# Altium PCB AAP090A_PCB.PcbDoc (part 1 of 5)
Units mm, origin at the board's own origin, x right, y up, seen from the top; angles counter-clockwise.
Board outline 160 x 130 mm, 4 copper layers (Top Layer, Signal Layer 1, Signal Layer 2, Bottom Layer), stack 1.567 mm thick; 507 components, 275 nets, 1462 pads, 1041 vias.
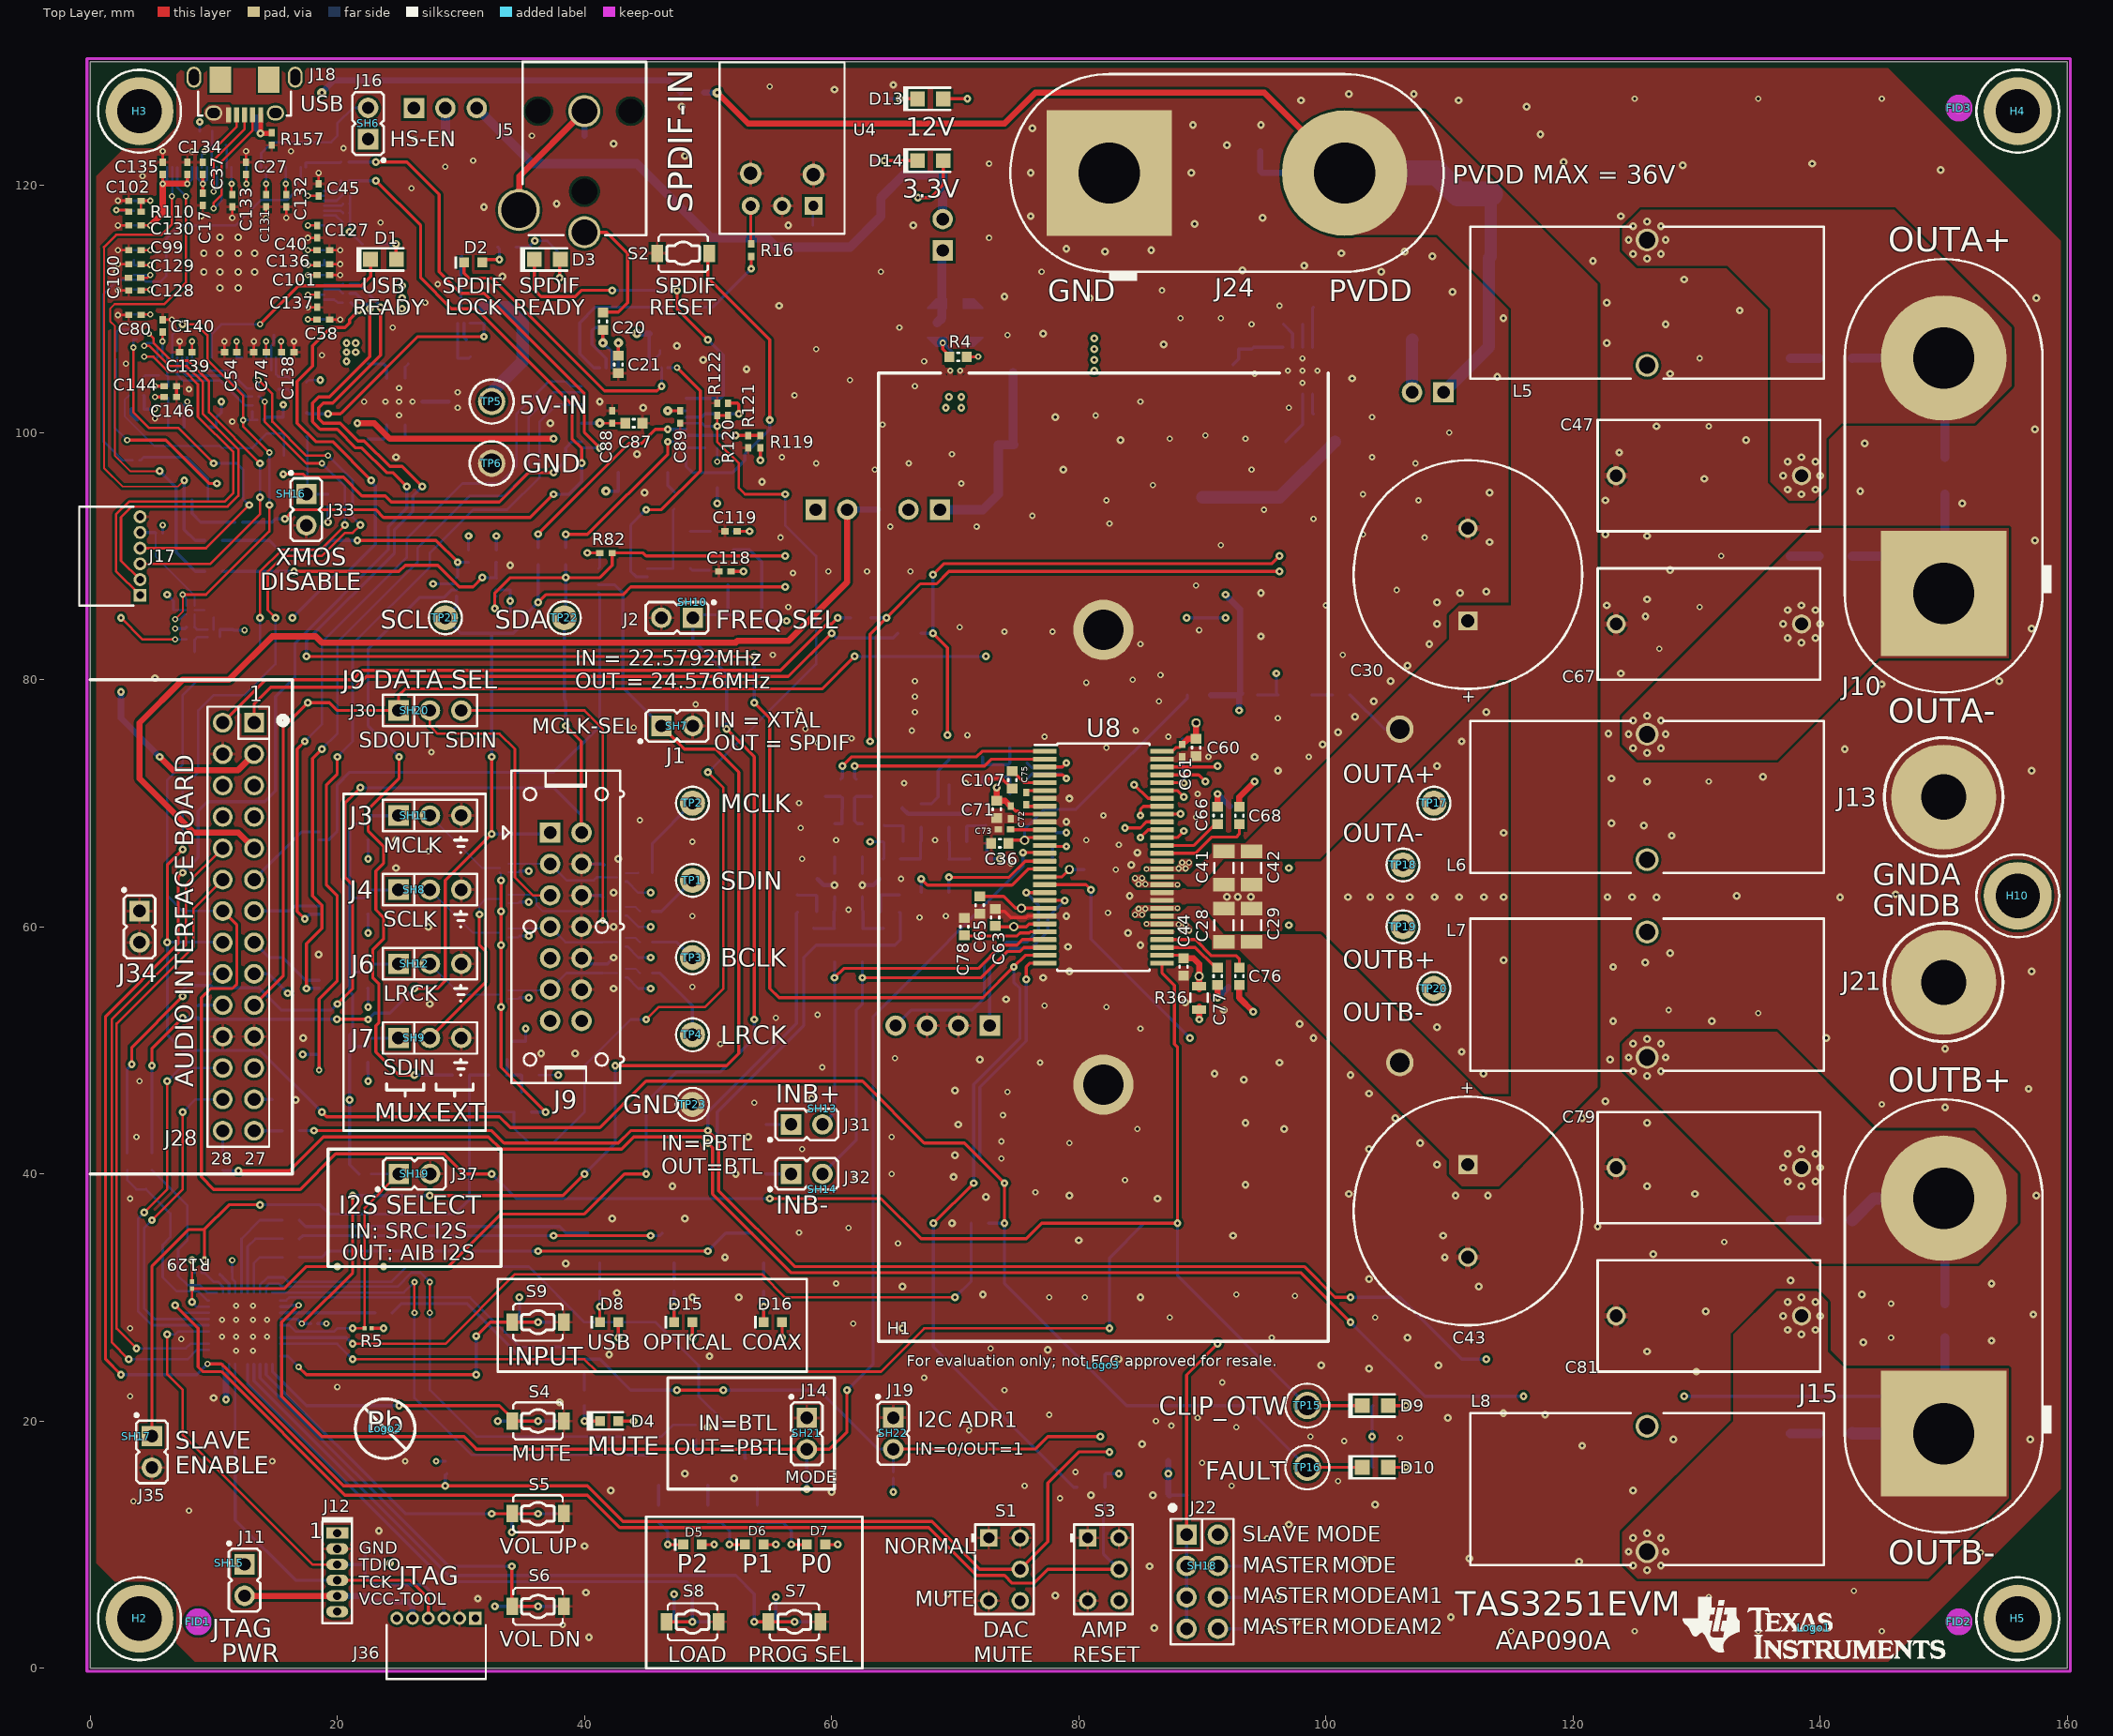
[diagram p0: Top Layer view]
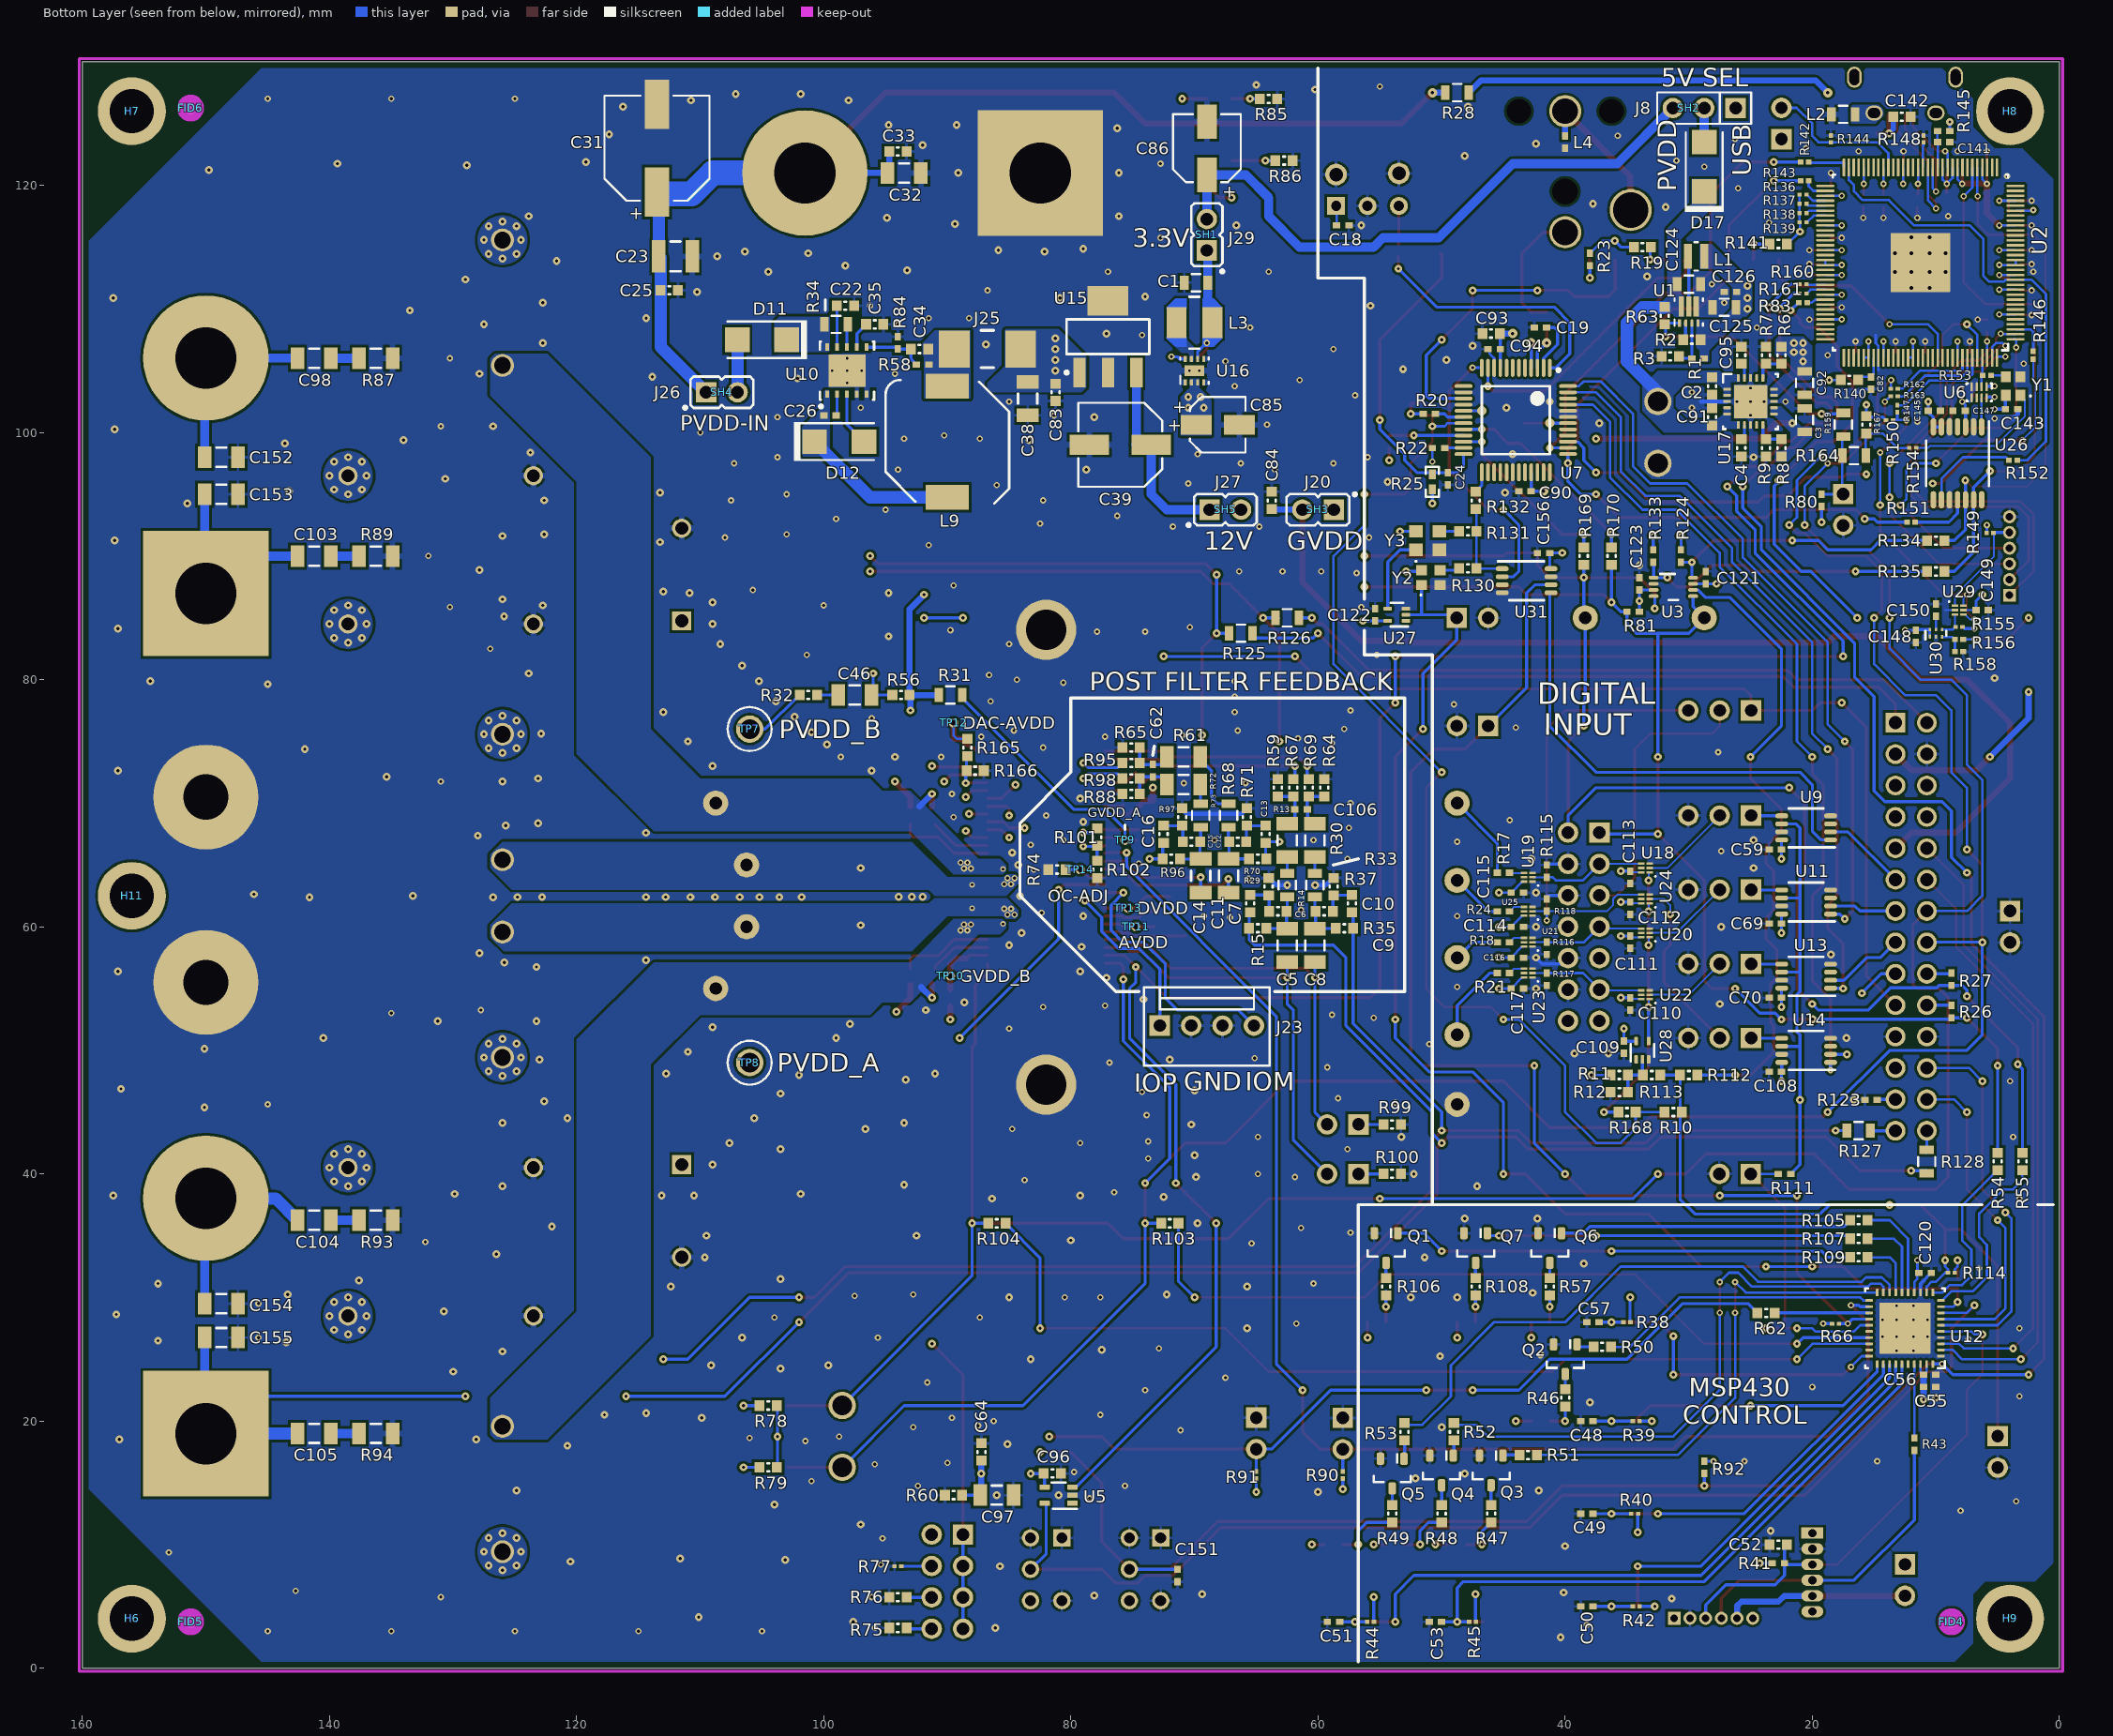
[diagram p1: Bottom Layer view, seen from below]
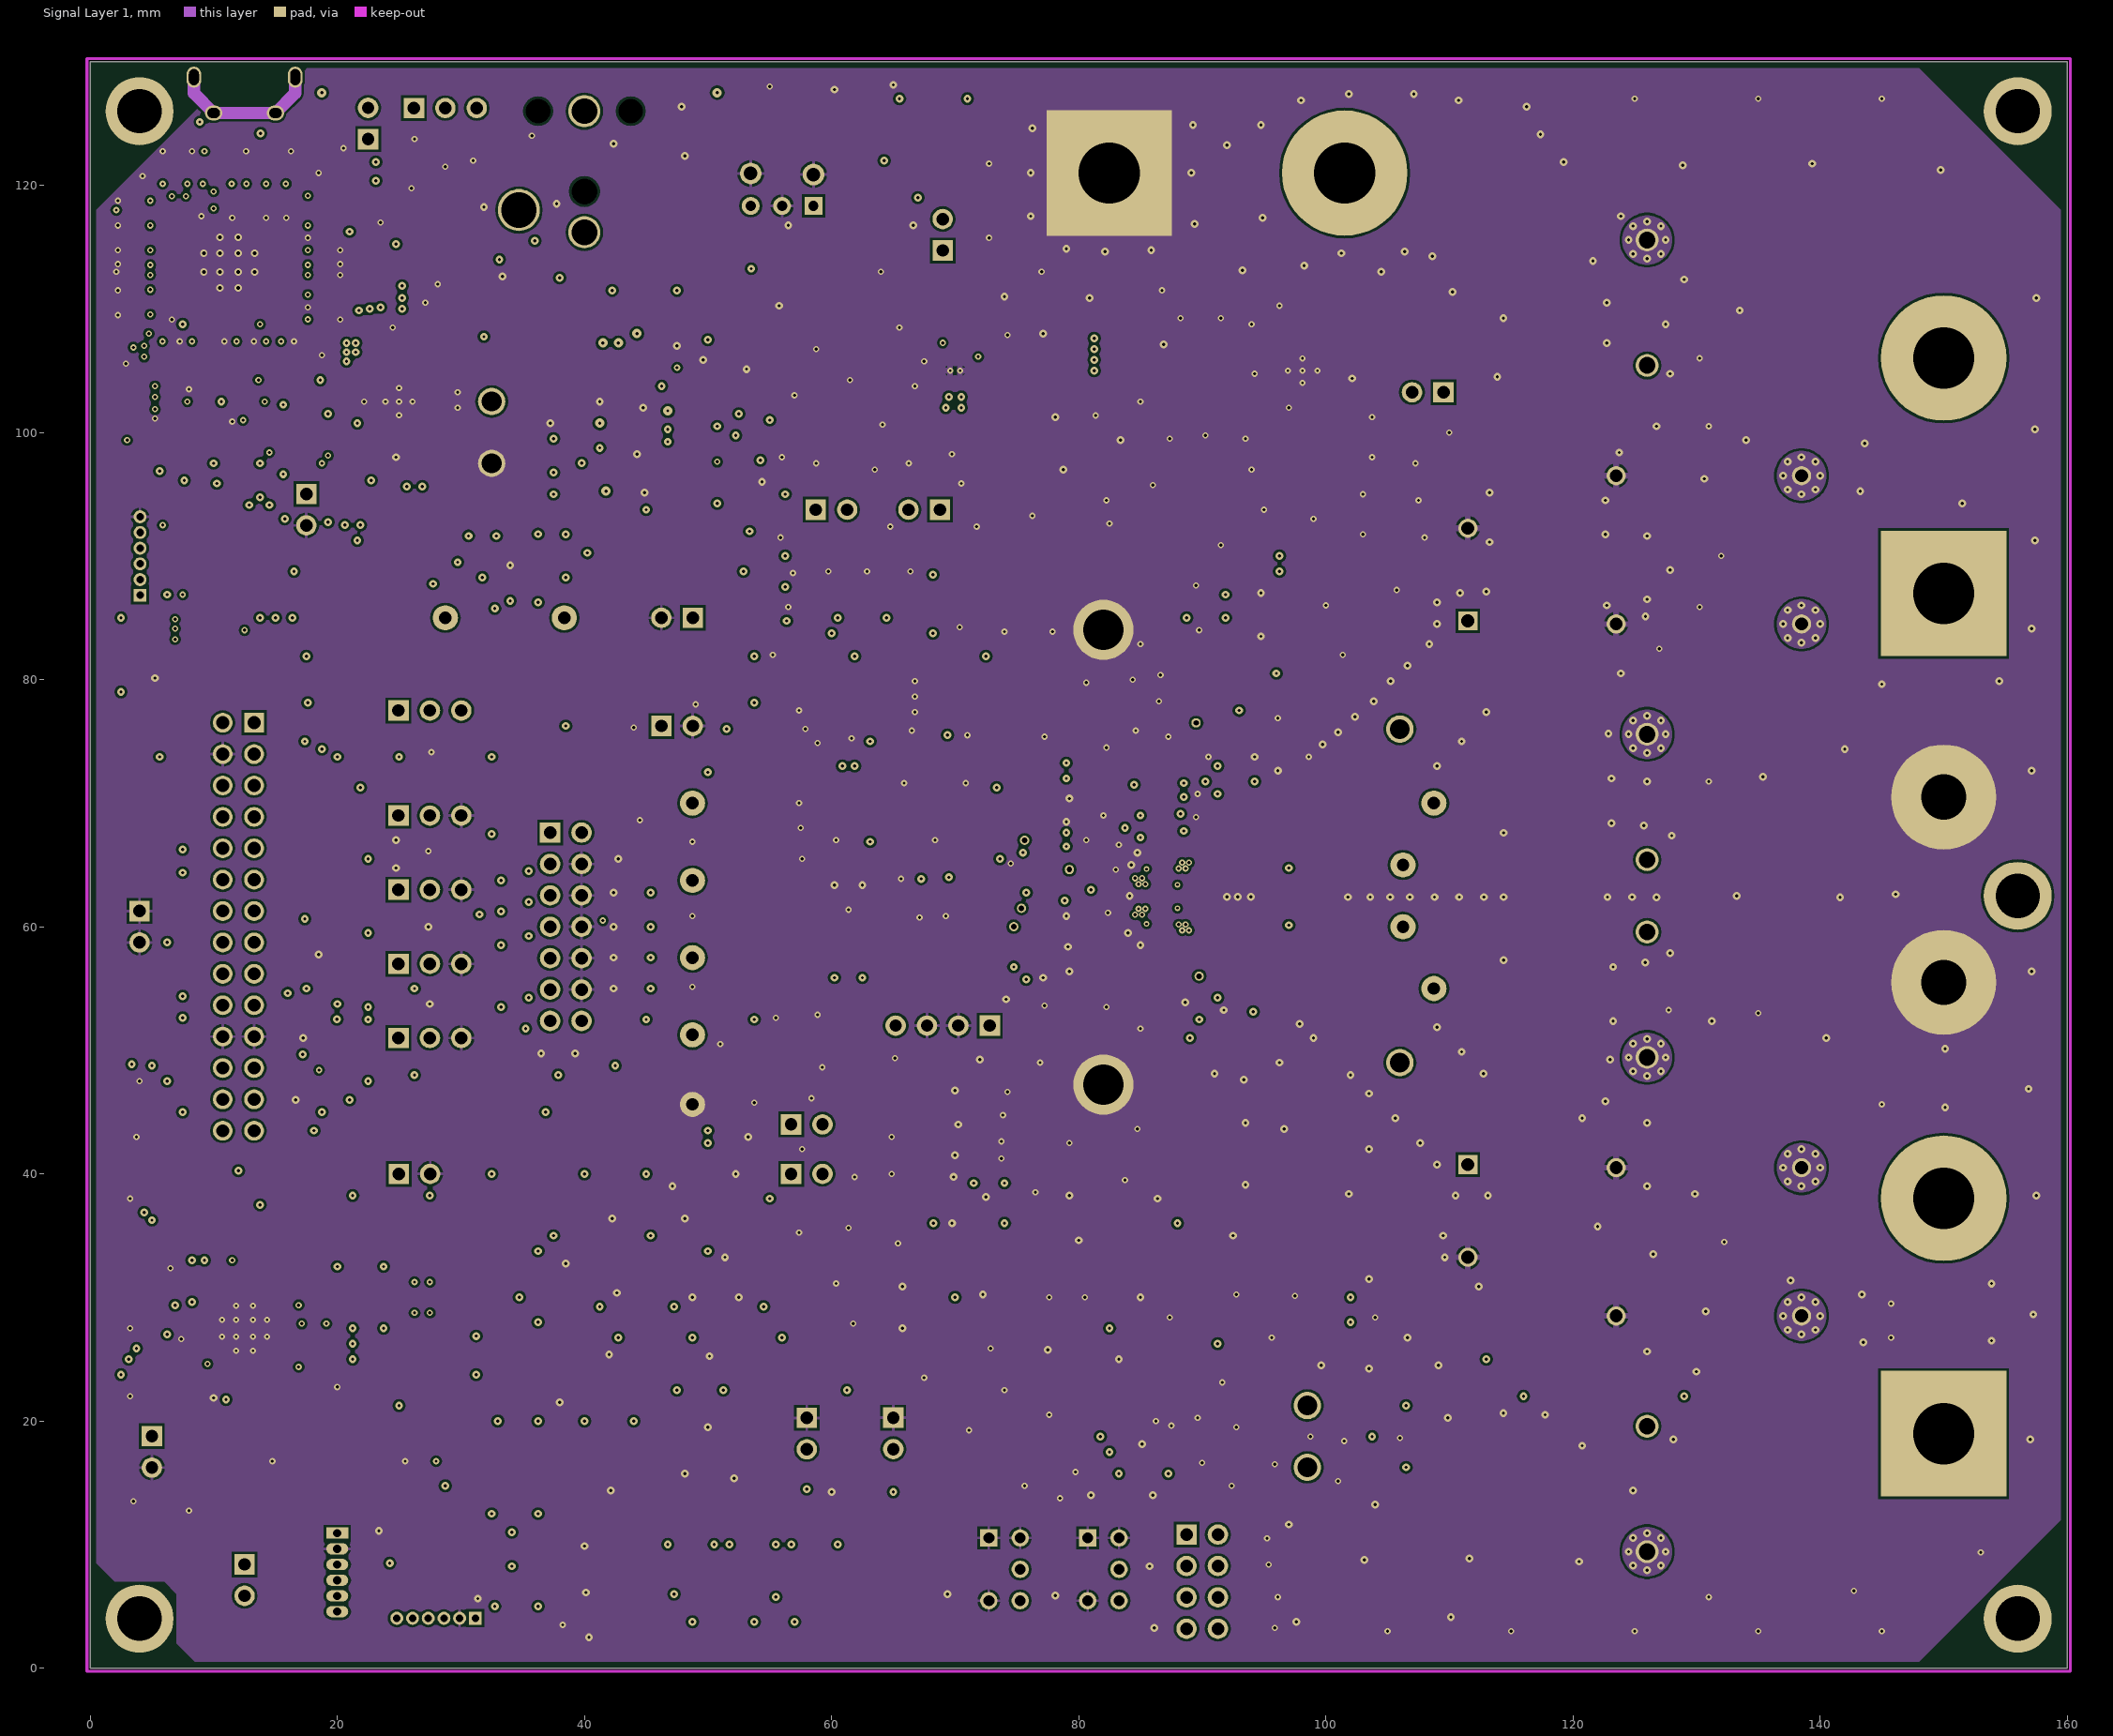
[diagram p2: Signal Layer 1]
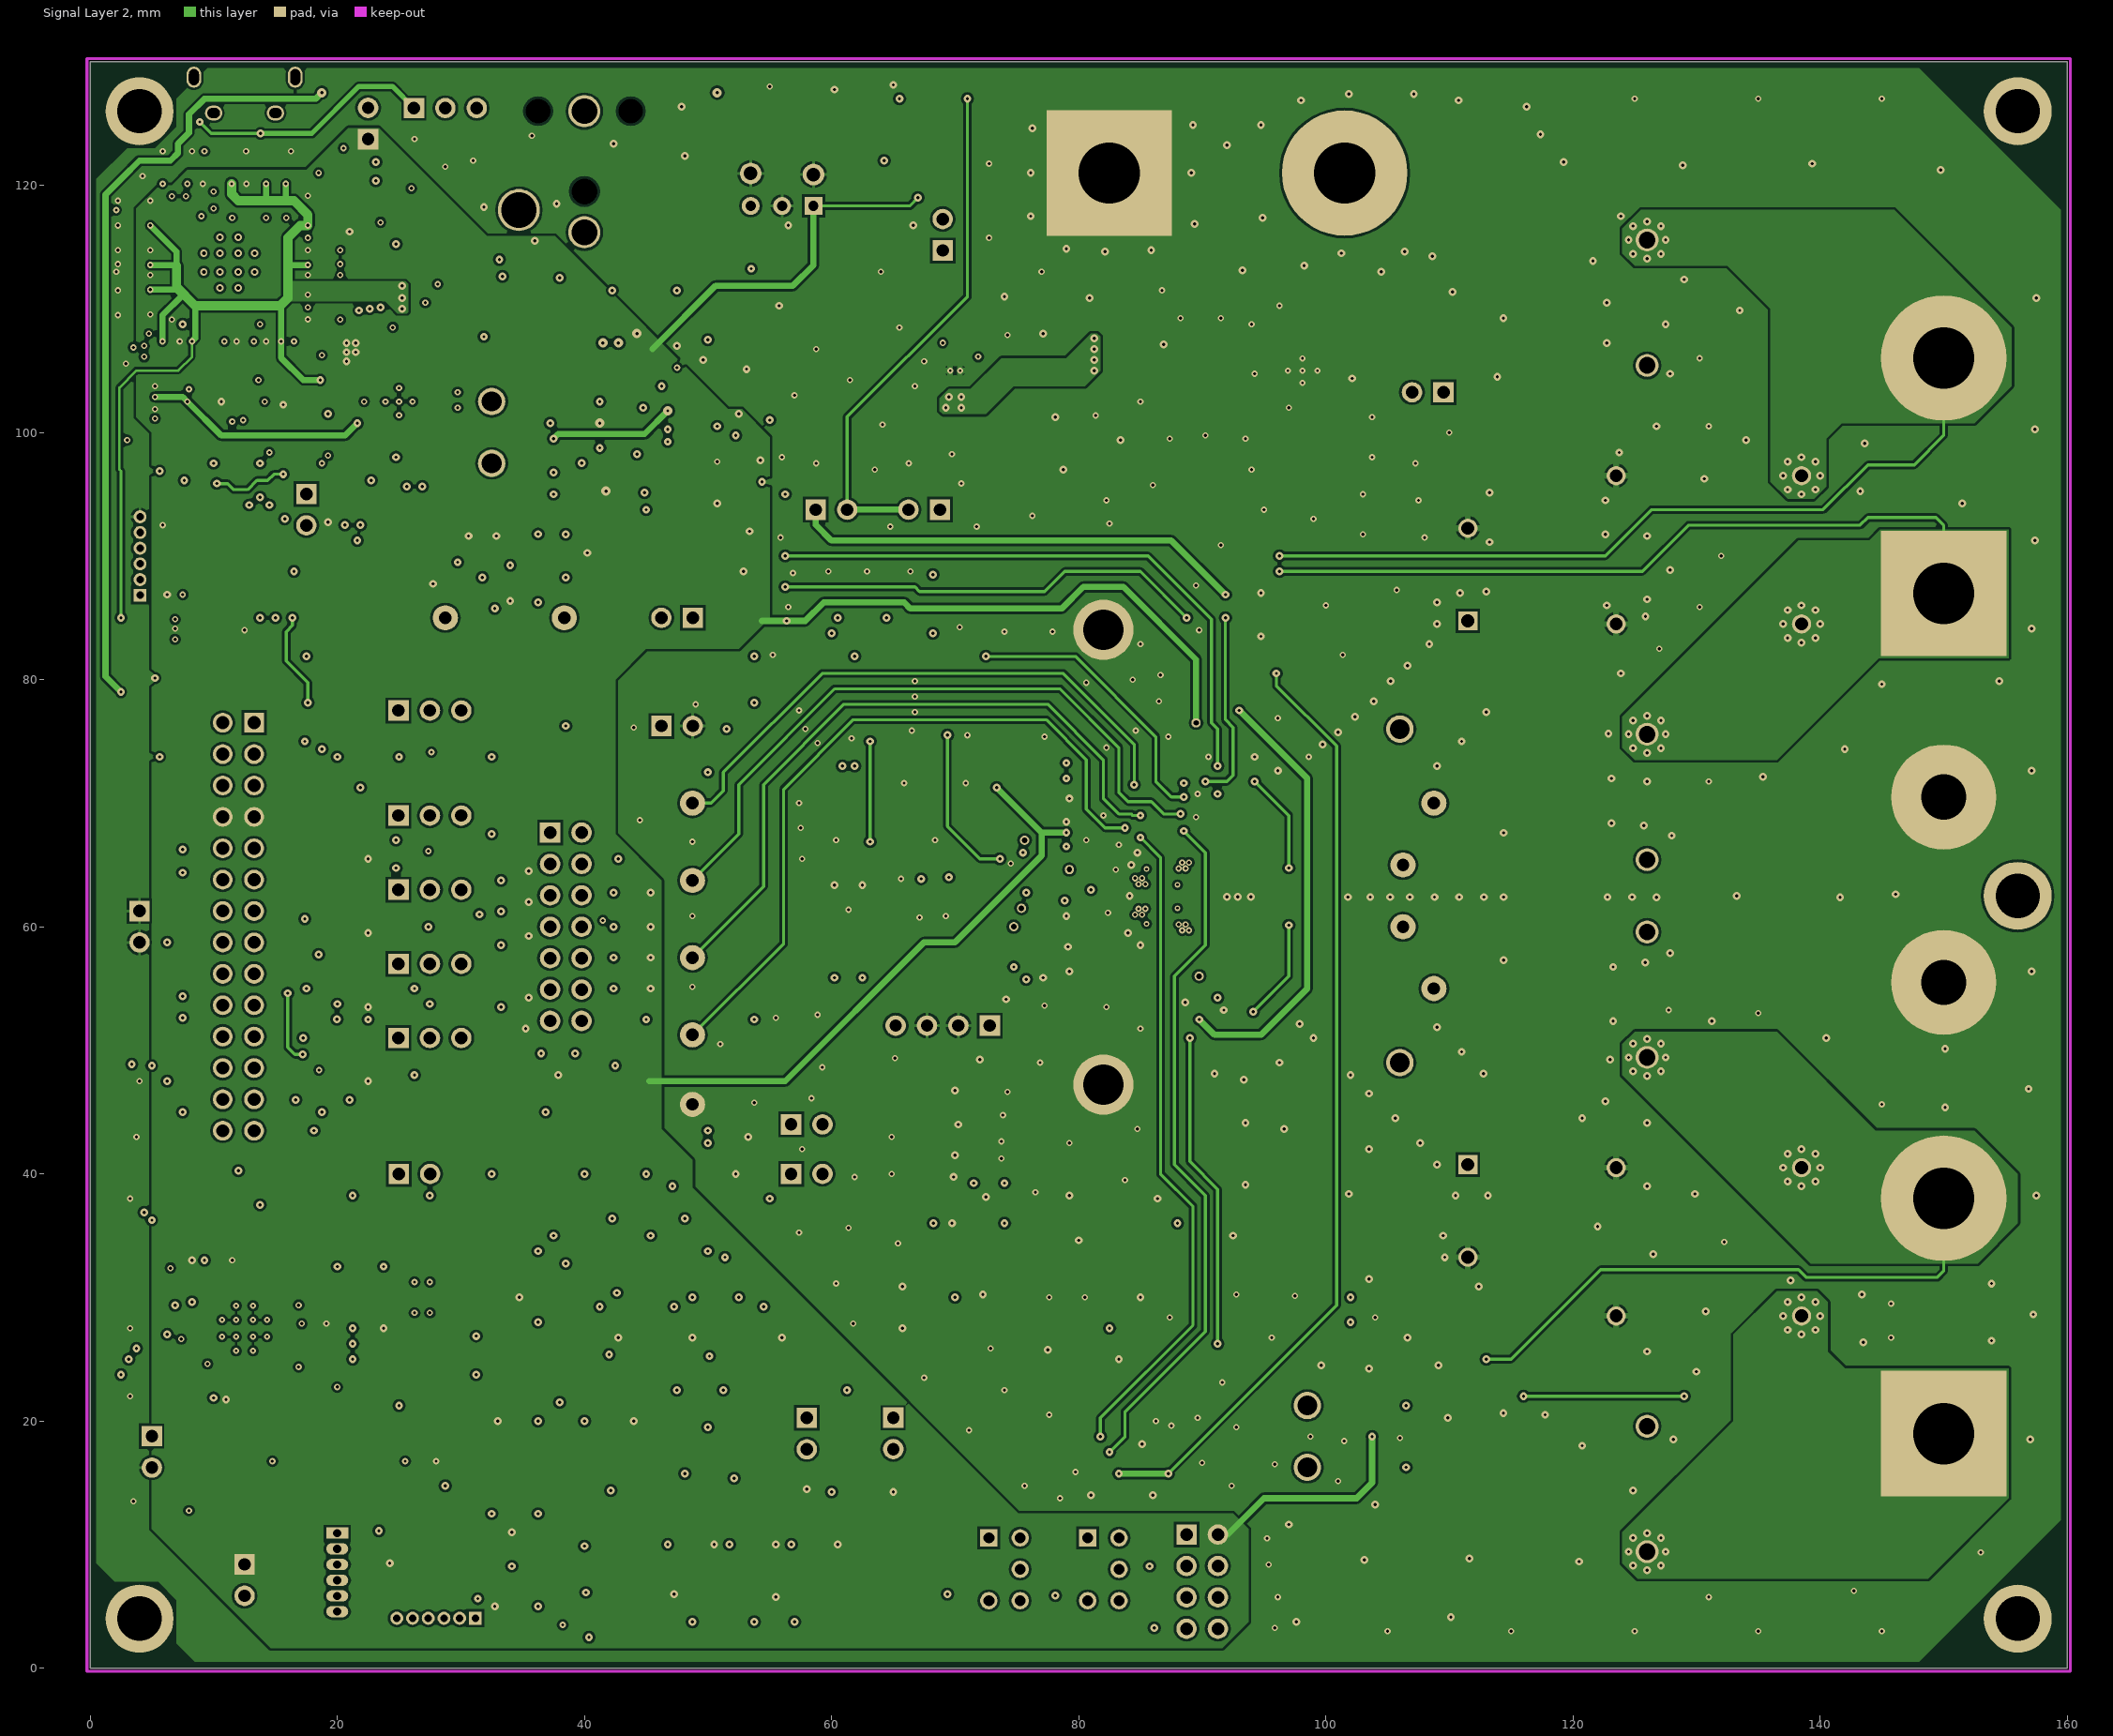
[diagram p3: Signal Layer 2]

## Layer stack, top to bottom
Top Solder: solder mask 0.0102, Solder Resist, Dk 3.5
Top Layer: signal copper 0.0696
Dielectric 1: prepreg 0.2032, FR-4, Dk 4.2
Signal Layer 1: signal copper 0.0356
Dielectric 2: core 0.9505, FR-4, Dk 4.2
Signal Layer 2: signal copper 0.0356
Dielectric 3: prepreg 0.2032, FR-4, Dk 4.2
Bottom Layer: signal copper 0.0696
Bottom Solder: solder mask 0.0102, Solder Resist, Dk 3.5

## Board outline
0,0 160,0 160,130 0,130

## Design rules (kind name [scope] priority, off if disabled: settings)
AcuteAngle [All] p1: minimum=4.50000000000000E+0001 checktracksonly=FALSE
AssemblyTestPointUsage [All] p1: valid=2
BoardOutlineClearance "BOC For Jacks at Edge" [InComponent('J18')] p1: gap=0 ignorepadtopadclearanceinfootprint=FALSE
BoardOutlineClearance BoardOutlineClearance_MountingHoles [OnCopper and InComponentClass('Mounting Holes')] p2: gap=0.25 ignorepadtopadclearanceinfootprint=FALSE
BoardOutlineClearance BoardOutlineClearance_Poly [OnCopper and IsPoly] p3: gap=0.5 ignorepadtopadclearanceinfootprint=FALSE
BoardOutlineClearance [OnCopper and Not InComponentClass('Logo') and not InComponentClass('FiducialMark') and not InRegion(1000,500,4000,800) and not InPoly] p4: gap=0.5 ignorepadtopadclearanceinfootprint=FALSE
Clearance "Fiducial Rules Error" [InComponent('FID*')] p1: gap=0.2 ignorepadtopadclearanceinfootprint=TRUE except(0: Arc-SMDPad Arc-Hole Track-SMDPad Track-Hole SMDPad-Hole THPad-Hole Via-Hole Fill-Hole Poly-Hole Region-Hole Text-Hole)
Clearance "Clearance LibErrors" [HasFootprint('DSF*') or HasFootprint('RLT*')] p2: gap=0.2 ignorepadtopadclearanceinfootprint=FALSE except(0: Arc-Hole Track-Hole SMDPad-Hole THPad-Hole Via-Hole Fill-Hole Poly-Hole Region-Hole Text-Hole; 0.1: Track-SMDPad SMDPad-SMDPad)
Clearance Clearance_Keepouts [((IsTrack Or IsArc) And Not InPoly) And IsFree and IsKeepOut vs ((IsTrack Or IsArc) And Not InPoly) And IsFree and IsKeepOut] p3: gap=0 ignorepadtopadclearanceinfootprint=FALSE
Clearance Clearance_Poly [InPolygon] p4: gap=0.2 ignorepadtopadclearanceinfootprint=TRUE except(0: Arc-Hole Track-Hole SMDPad-Hole THPad-Hole Via-Hole Fill-Hole Poly-Hole Region-Hole Text-Hole)
Clearance [All] p5: gap=0.2 ignorepadtopadclearanceinfootprint=FALSE except(0: Arc-Hole Track-Hole SMDPad-Hole THPad-Hole Via-Hole Fill-Hole Poly-Hole Region-Hole Text-Hole)
ComponentClearance "CompClearance for Heatsink" [InComponent('H1')] p1: gap=0 collisioncheckmode=3 verticalgap=0 showdistances=FALSE
ComponentClearance ComponentClearance_MountingHoles_FiducialMarks [InComponentClass('Mounting Holes') vs InComponentClass('FiducialMark')] p2: gap=0.25 collisioncheckmode=3 verticalgap=0 showdistances=FALSE
ComponentClearance ComponentClearance_Shunt [InComponentClass('Header') vs InComponentClass('Shunt')] p3: gap=0 collisioncheckmode=3 verticalgap=0 showdistances=FALSE
ComponentClearance ComponentClearance_Logo [InComponentClass('Logo')] p4: gap=0 collisioncheckmode=3 verticalgap=0 showdistances=FALSE
ComponentClearance ComponentClearance_MountingHoles [InComponentClass('Mounting Holes')] p5: gap=0 collisioncheckmode=3 verticalgap=0 showdistances=FALSE
ComponentClearance ComponentClearance_SmallPassives [HasFootprint('0201*') or HasFootprint('0402*') or HasFootprint('0508') or HasFootprint('0603*') or HasFootprint('0612') or HasFootprint('0805*') or HasFootprint('0815*') or HasFootprint('0830*') or HasFootprint('1206*') or HasFootprint('1210*') or HasFootprint('1808*') or HasFootprint('1812*') or HasFootprint('1825*') or HasFootprint('2010*') or HasFootprint('2220*') or HasFootprint('2225*') or HasFootprint('2512*') or HasFootprint('2728*') or HasFootprint('3518*') or HasFootprint('DKQ*') or HasFootprint('OSC*') or HasFootprint('PFB*') or HasFootprint('RHB*') or HasFootprint('SOT*') or HasFootprint('XTAL*') vs HasFootprint('0201*') or HasFootprint('0402*') or HasFootprint('0508') or HasFootprint('0603*') or HasFootprint('0612') or HasFootprint('0805*') or HasFootprint('0815*') or HasFootprint('0830*') or HasFootprint('1206*') or HasFootprint('1210*') or HasFootprint('1808*') or HasFootprint('1812*') or HasFootprint('1825*') or HasFootprint('2010*') or HasFootprint('2220*') or HasFootprint('2225*') or HasFootprint('2512*') or HasFootprint('2728*') or HasFootprint('3518*') or HasFootprint('DKQ*') or HasFootprint('OSC*') or HasFootprint('PFB*') or HasFootprint('RHB*') or HasFootprint('SOT*') or HasFootprint('XTAL*')] p6: gap=0.25 collisioncheckmode=3 verticalgap=0 showdistances=FALSE
ComponentClearance ComponentClearance_THtoSMT [IsThruComponent vs IsSMTComponent] p7: gap=0.25 collisioncheckmode=3 verticalgap=0 showdistances=FALSE
ComponentClearance ComponentClearance_THtoTH [IsThruComponent vs IsThruComponent] p8: gap=0.25 collisioncheckmode=3 verticalgap=0 showdistances=FALSE
ComponentClearance [All] p9: gap=0.25 collisioncheckmode=3 verticalgap=0 showdistances=FALSE
DiffPairsRouting [All] p1: maxlimit=2.54 minlimit=0.254 mostfreqgap=0.254 toplayer_minwidth=0.381 toplayer_maxwidth=0.381 toplayer_prefwidth=0.381 midlayer1_minwidth=0.381 midlayer1_maxwidth=0.381 midlayer1_prefwidth=0.381 midlayer2_minwidth=0.381 midlayer2_maxwidth=0.381 midlayer2_prefwidth=0.381 bottomlayer_minwidth=0.381 bottomlayer_maxwidth=0.381 bottomlayer_prefwidth=0.381 maxuncoupledlength=25.4
FabricationTestPointUsage TestPointUsage [All] p1: valid=2 allowmultiple=FALSE
FabricationTestpoint Testpoint [All] p1: side=3 testpointundercomponent=TRUE minsize=1.016 maxsize=2.54 preferedsize=1.524 minholesize=0 maxholesize=1.016 preferedholesize=0.813 testpointgrid=0.025 allowsidetop=TRUE allowsidebottom=TRUE usegrid=TRUE gridtolerance=0
FanoutControl Fanout_LCC [IsLCC] p1: bgadir=Out bgaviamode=Centered fanoutstyle=Auto fanoutdirection=Alternating viagrid=0.025 // Fanout_LCC (Default Rule)
FanoutControl Fanout_BGA [IsBGA] p2: bgadir=Out bgaviamode=Centered fanoutstyle=Auto fanoutdirection=Alternating viagrid=0.025 // Fanout_BGA (Default Rule)
FanoutControl Fanout_Default [All] p4: bgadir=Out bgaviamode=Centered fanoutstyle=Auto fanoutdirection=Alternating viagrid=0.025 // Fanout_Default (Default Rule)
FanoutControl Fanout_Small [(CompPinCount < 5)] p5: bgadir=Out bgaviamode=Centered fanoutstyle=Auto fanoutdirection=OutThenIn viagrid=0.025 // Fanout_Small (Default Rule)
Height [All] p1: minheight=0 maxheight=38.1 prefheight=12.7
HoleSize [All] p1: absolutevalues=TRUE maxlimit=6.375 minlimit=0.2 maxpercent=80.000 minpercent=20.000
MinimumAnnularRing MinimumAnnularRing_ThermalPadVias [IsVia and InAnyComponent] p1: minimumring=0.15
MinimumAnnularRing [All] p2: minimumring=0.127
MinimumSolderMaskSliver "MinSolderMaskSliver LibErrors" [HasFootprint('DCU*') or HasFootprint('DQM*') or HasFootprint('DRL*') or HasFootprint('DSF*') or HasFootprint('PFB*') or HasFootprint('PW*') or HasFootprint('TQFP*')] p1: minsoldermaskwidth=0.064
MinimumSolderMaskSliver MinimumSolderMaskSliver_Logo [InComponentClass('Logo') vs InComponentClass('Logo')] p2: minsoldermaskwidth=0.018
MinimumSolderMaskSliver [All] p3: minsoldermaskwidth=0.102
PlaneConnect [All] p1: planeconnectstyle=Relief reliefexpansion=0.254 reliefentries=4 reliefconductorwidth=0.254 reliefairgap=0.254
PolygonConnect "PostFlood GND" [InComponent('C16') or InComponent('C28') or InComponent('C29') or  InComponent('C31') or InComponent('C41') or InComponent('C42') or  InComponent('C44') or InComponent('C55') or InComponent('C56') or  InComponent('C60') or InComponent('C61') or InComponent('C63') or  InComponent('C65') or InComponent('C71') or InComponent('C72') or  InComponent('C73') or InComponent('C78') or InComponent('C124') or  InComponent('C125') or InComponent('C126')  or InComponent('J13') or InComponent('J21') or InComponent('J24') or InComponent('R74') or  InComponent('U1') vs InNet('GND')] p1: connectstyle=Direct reliefconductorwidth=0.254 reliefentries=4 polygonreliefangle="90 Angle" airgapwidth=0.254
PolygonConnect "GND Thermals 0.5mm" [InComponent('C23') or InComponent('C30') or  InComponent('C32') or InComponent('C39') or  InComponent('C43') or InComponent('C47') or  InComponent('C67') or InComponent('C79') or  InComponent('C81') or InComponent('C85') or  InComponent('C86') or InComponent('L2') or  InComponent('R87') or InComponent('R89') or  InComponent('R93') or InComponent('R94') or  InComponent('U16') vs InNet('GND')] p2: connectstyle=Relief reliefconductorwidth=0.5 reliefentries=4 polygonreliefangle="90 Angle" airgapwidth=0.2
PolygonConnect "GND Thermals 0.25mm" [InComponent('C*') or InComponent('D*') or InComponent('J*') or InComponent('Q*') or InComponent('R*') or InComponent('S*') or InComponent('U1') or InComponent('U4') vs InNet('GND')] p3: connectstyle=Relief reliefconductorwidth=0.25 reliefentries=4 polygonreliefangle="90 Angle" airgapwidth=0.2
PolygonConnect PreFlood [All] p4: connectstyle=Direct reliefconductorwidth=0.254 reliefentries=4 polygonreliefangle="90 Angle" airgapwidth=0.254
RoutingVias ThermalPadVias [IsVia and InAnyComponent] p1: holewidth=0.2 width=0.5 viastyle="Through Hole" minholewidth=0.2 minwidth=0.5 maxholewidth=0.33 maxwidth=0.6
RoutingVias [All] p2: holewidth=0.406 width=0.864 viastyle="Through Hole" minholewidth=0.2 minwidth=0.457 maxholewidth=1.016 maxwidth=1.651
SilkToBoardRegionClearance [Not ((IsComment or IsDesignator) And (Hide <> 'False')) and not InRegion(1000,500,4000,800)] p1:
SilkToSilkClearance SilkToSilkClearance_Pb-FreeLogo [(HasFootprint('Pb-Free_Overlay_Medium') OR HasFootprint('Pb-Free_Overlay_Small')) vs (HasFootprint('Pb-Free_Overlay_Medium') OR HasFootprint('Pb-Free_Overlay_Small'))] p1: silktosilkclearance=0
SilkToSilkClearance [All] p2: silktosilkclearance=0.102
SilkToSolderMaskClearance SilkToComponentPadClearance [IsPad and InAnycomponent] p1: minsilkscreentomaskgap=0.127 clearancetoexposedcopper=TRUE
SilkToSolderMaskClearance "Silk to Solder Mask Opening" [All] p2: minsilkscreentomaskgap=0.102 clearancetoexposedcopper=FALSE
SolderMaskExpansion [All] p1: expansion=0.05
Width [All] p1: maxlimit=2.54 minlimit=0.15 preferedwidth=0.254 toplayer_minwidth=0.152 midlayer1_minwidth=0.152 midlayer2_minwidth=0.152 minimp=50.000000 maximp=50.000000 favimp=50.000000 checkconnectedcopper=TRUE
14 further rules are at their usual default settings.

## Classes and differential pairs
component class Shunt: SH1 SH2 SH3 SH4 SH5 SH6 SH7 SH8 SH9 SH10 SH11 SH12 SH13 SH14 SH15 SH16 SH17 SH18 SH19 SH20 SH21 SH22
component class Logo: Logo1
component class AAP090A_EVM_Hardware: FID1 FID2 FID3 FID4 FID5 FID6 H2 H3 H4 H5 H6 H7 H8 H9 H10 H11 Logo1 Logo2 Logo3 SH1 SH2 SH3 SH4 SH5 SH6 SH7 SH8 SH9 SH10 SH11 SH12 SH13 SH14 SH15 SH16 SH17 SH18 SH19 SH20 SH21 SH22 ZZ1 ZZ2 ZZ3
component class FiducialMark: FID1 FID2 FID3 FID4 FID5 FID6
component class AssemblyNote: ZZ1 ZZ2 ZZ3
component class AAP090A_MSP430: C46 C48 C49 C50 C51 C52 C53 C55 C56 C57 C64 C96 C97 C109 C151 D4 D5 D6 D7 D8 D15 D16 J2 J11 J12 J35 J36 J37 Q1 Q2 Q3 Q4 Q5 Q6 Q7 R5 R10 R32 R38 R39 R40 R41 R42 R43 R44 R45 R46 R47 R48 R49 R50 R51 R52 R53 R54 R55 R56 R57 R60 R62 R92 R103 R104 R105 R106 R107 R108 R109 R111 R112 R113 R114 R129 S1 S3 S4 S5 S6 S7 S8 S9 U5 U12
component class AAP090A_PowerSupplies: C1 C2 C3 C4 C22 C23 C25 C26 C31 C32 C33 C34 C35 C38 C39 C83 C84 C85 C86 C87 C88 C89 C90 C91 C92 C93 C94 C95 D11 D12 D13 D14 D17 J8 J24 J25 J26 J27 J29 L3 L9 R4 R6 R7 R8 R9 R34 R58 R84 R85 R86 TP5 TP6 U10 U15 U16 U17
component class AAP090A_SPDIF-SRC4392: C18 C19 C20 C21 C24 C59 C69 C70 C108 C110 C111 C112 C113 C114 C115 C116 C117 C118 C119 C120 C121 C122 C123 C156 D2 D3 J1 J3 J4 J5 J6 J7 J9 J28 J30 J34 L4 R11 R12 R16 R17 R18 R19 R20 R21 R22 R23 R24 R25 R26 R27 R28 R66 R115 R116 R117 R118 R119 R120 R121 R122 R123 R130 R131 R132 R168 R169 R170 S2 U4 U7 U9 U11 U13 U14 U18 U19 U20 U21 U22 U23 U24 U25 U27 U28 U31 Y2 Y3
component class AAP090A_TAS3251DKQ-IO: C5 C6 C7 C8 C9 C10 C11 C12 C13 C14 C15 C16 C28 C29 C30 C36 C41 C42 C43 C44 C47 C60 C61 C62 C63 C65 C66 C67 C68 C71 C72 C73 C75 C76 C77 C78 C79 C81 C98 C103 C104 C105 C106 C107 C152 C153 C154 C155 D9 D10 H1 J10 J13 J14 J15 J19 J20 J21 J22 J23 J31 J32 L5 L6 L7 L8 R13 R14 R15 R29 R30 R31 R33 R35 R36 R37 R59 R61 R64 R65 R67 R68 R69 R70 R71 R72 R73 R74 R75 R76 R77 R78 R79 R87 R88 R89 R90 R91 R93 R94 R95 R96 R97 R98 R99 R100 R101 R102 R125 R126 R127 R128 R165 R166 TP1 TP2 TP3 TP4 TP7 TP8 TP9 TP10 TP11 TP12 TP13 TP14 TP15 TP16 TP17 TP18 TP19 TP20 TP21 TP22 TP23 U8
component class AAP090A_XMOS: C17 C27 C37 C40 C45 C54 C58 C74 C80 C82 C99 C100 C101 C102 C124 C125 C126 C127 C128 C129 C130 C131 C132 C133 C134 C135 C136 C137 C138 C139 C140 C141 C142 C143 C144 C145 C146 C147 C148 C149 C150 D1 J16 J17 J18 J33 L1 L2 R1 R2 R3 R63 R80 R81 R82 R83 R110 R124 R133 R134 R135 R136 R137 R138 R139 R140 R141 R142 R143 R144 R145 R146 R147 R148 R149 R150 R151 R152 R153 R154 R155 R156 R157 R158 R159 R160 R161 R162 R163 R164 R167 U1 U2 U3 U6 U26 U29 U30 Y1
component class Header: J1 J2 J3 J4 J6 J7 J8 J11 J14 J16 J19 J20 J22 J26 J27 J29 J30 J31 J32 J33 J34 J35 J37
component class "Mounting Holes": H2 H3 H4 H5 H6 H7 H8 H9 H10 H11 H12 H13 H14 H15

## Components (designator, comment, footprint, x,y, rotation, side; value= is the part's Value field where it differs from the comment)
C1 "GRM21BZ71A226ME15L" 0805_KTR 69.875,112.125 r0 bottom value=22uF
C2 "GRM188R61A106ME69D" 0603L 28.125,103.75 r270 bottom value=10uF
C3 "GRM21BZ71A226ME15L" 0805_KTR 20.625,101 r90 bottom value=22uF
C4 "GRM188R71C105KA12D" 0603L 25.75,98.75 r90 bottom value=1uF
C5 "GRM31CR71C106KAC7L" 1206_180L 62.5,58.5 r270 bottom value=10uF
C6 "DNP" 0603L 63.25,61.25 r0 bottom value=220pF
C7 "DNP" 0603L 65.5,61.875 r90 bottom value=22pF
C8 "GRM31CR71C106KAC7L" 1206_180L 60.25,58.5 r270 bottom value=10uF
C9 "DNP" 0603L 59.5,61.25 r180 bottom value=220pF
C10 "DNP" 0603L 57.25,61.875 r90 bottom value=22pF
C11 "GRM31CR71C106KAC7L" 1206_180L 67.25,64.125 r270 bottom value=10uF
C12 "DNP" 0603L 66.5,66.875 r180 bottom value=220pF
C13 "DNP" 0603L 64.25,67.5 r90 bottom value=22pF
C14 "GRM31CR71C106KAC7L" 1206_180L 69.5,64.125 r270 bottom value=10uF
C15 "DNP" 0603L 70.25,66.875 r0 bottom value=220pF
C16 "DNP" 0603L 72.5,67.5 r90 bottom value=22pF
C17 "GRM155R71C104KA88D" 0402L 9.125,118.875 r90 top value=0.1uF
C18 "GRM155R71A104KA01D" 0402L 58,116.75 r180 bottom value=0.1uF
C19 "GRM155R71A104KA01D" 0402L 42,108.5 r180 bottom value=0.1uF
C20 "GRM188R71C104KA01D" 0603L 41.5,109 r90 top value=0.1uF
C21 "GRM188R71C104KA01D" 0603L 42.75,105.5 r270 top value=0.1uF
C22 "C0603C104K5RACTU" 0603L 98.25,110.25 r180 bottom value=0.1uF
C23 "C1210C225K1RACTU" 1210_210L 112,114.25 r180 bottom value=2.2uF
C24 "GRM155R71C104KA88D" 0402L 49.5,96.25 r90 bottom value=0.1uF
C25 "GRM188R72A104KA35J" 0603L 112.5,111.5 r180 bottom value=0.1uF
C26 "GRM155R71E473KA88D" 0402L 99.5,101.375 r0 bottom value=0.047uF
C27 "GRM155R71C104KA88D" 0402L 12.625,121.375 r270 top value=0.1uF
C28 "GRM31CR72A105KA01L" 1206_180L 91.75,60.125 r270 top value=1uF
C29 "GRM31CR72A105KA01L" 1206_180L 94,60.125 r270 top value=1uF
C30 "+" FC_1800x3550 111.5,88.5 r90 top locked value=2200uF
C31 "+" SM_RADIAL_F 113.5,123 r90 bottom value=47uF
C32 "GRM31CR72A105KA01L" 1206_180L 93.5,121 r0 bottom value=1uF
C33 "06031C103KAT2A" 0603L 94,122.75 r180 bottom value=0.01uF
C34 "GRM188R71H562KA01D" 0603L 92.25,106.75 r0 bottom value=5600pF
C35 "C0603X472K5RACTU" 0603L 95.875,108.75 r180 bottom value=4700pF
C36 "C0603C104K5RACTU" 0603L 73.625,66.75 r180 top value=0.1uF
C37 "GRM155R71C104KA88D" 0402L 9.125,121.375 r270 top value=0.1uF
C38 "GRM31CR71E475KA88L" 1206_180L 83.5,102.75 r270 bottom value=4.7uF
C39 "+" SM_RADIAL_D 76,99 r0 bottom value=47uF
C40 "GRM155R71C104KA88D" 0402L 18.875,114.75 r180 top value=0.1uF
C41 "GRM31CR72A105KA01L" 1206_180L 91.75,64.75 r90 top value=1uF
C42 "GRM31CR72A105KA01L" 1206_180L 94,64.75 r90 top value=1uF
C43 "+" FC_1800x3550 111.5,37 r270 top locked value=2200uF
C44 "C0603C104K5RACTU" 0603L 88.5,56.75 r270 top value=0.1uF
C45 "GRM155R71C104KA88D" 0402L 18.5,119.625 r270 top value=0.1uF
C46 "GRM31CR72A105KA01L" 1206_180L 97.5,78.75 r0 bottom value=1uF
C47 "B32652A3684J" B32652_1800x900x1750 131,96.5 r180 top locked value=0.68uF
C48 "GRM1555C1E471JA01D" 0402L 38.25,20 r0 bottom value=470pF
C49 "GRM1555C1E471JA01D" 0402L 38.25,12.5 r0 bottom value=470pF
C50 "GRM1555C1E471JA01D" 0402L 38.25,5 r0 bottom value=470pF
C51 "GRM1555C1E471JA01D" 0402L 58.75,3.75 r0 bottom value=470pF
C52 "885012206036" 0603L 22.75,10 r180 bottom value=2200pF
C53 "GRM1555C1E471JA01D" 0402L 50.5,3.75 r0 bottom value=470pF
C54 "GRM155R71C104KA88D" 0402L 11.375,106.5 r0 top value=0.1uF
C55 "GRM152R60J105ME15D" 0402L 10.5,22.75 r0 bottom value=1uF
C56 "GRM155R71A104KA01D" 0402L 10.5,23.75 r0 bottom value=0.1uF
C57 "GRM1555C1E471JA01D" 0402L 37.75,28 r0 bottom value=470pF
C58 "GRM155R71C104KA88D" 0402L 18.875,109.125 r180 top value=0.1uF
C59 "GRM155R71A104KA01D" 0402L 23,66.25 r180 bottom value=0.1uF
C60 "GRM188R61A106ME69D" 0603L 89.5,74.5 r270 top value=10uF
C61 "GRM155R71A104KA01D" 0402L 88.375,74.25 r270 top value=0.1uF
C62 "GRM1555C1H102JA01D" 0402L 73.375,72.625 r270 bottom value=1000pF
C63 "GRM188R71C105KA12D" 0603L 73.25,60.75 r270 top value=1uF
C64 "C0603C104K5RACTU" 0603L 87.25,17.5 r90 bottom value=0.1uF
C65 "GRM188R71C105KA12D" 0603L 72,61.75 r90 top value=1uF
C66 "GRM188R71E333KA01D" 0603L 91.25,69 r270 top value=0.033uF
C67 "B32652A3684J" B32652_1800x900x1750 131,84.5 r180 top locked value=0.68uF
C68 "GRM188R71E333KA01D" 0603L 93,69 r270 top value=0.033uF
C69 "GRM155R71A104KA01D" 0402L 23,60.25 r180 bottom value=0.1uF
C70 "GRM155R71A104KA01D" 0402L 23,54.25 r180 bottom value=0.1uF
C71 "GRM188R61A106ME69D" 0603L 73.375,69.5 r270 top value=10uF
C72 "GRM155R71A104KA01D" 0402L 74.5,69.25 r270 top value=0.1uF
C73 "GRM155R71A104KA01D" 0402L 74,67.875 r180 top value=0.1uF
C74 "GRM155R71C104KA88D" 0402L 13.75,106.5 r0 top value=0.1uF
C75 "C1005X5R1A225K050BC" 0402L 75.75,70.375 r270 top value=2.2uF
C76 "GRM188R71E333KA01D" 0603L 93,56 r90 top value=0.033uF
C77 "GRM188R71E333KA01D" 0603L 91.25,56 r90 top value=0.033uF
C78 "GRM188R71H473KA61D" 0603L 70.75,60 r90 top value=0.047uF
C79 "B32652A3684J" B32652_1800x900x1750 131,40.5 r180 top locked value=0.68uF
C80 "GRM155R71C104KA88D" 0402L 3.625,109.5 r0 top value=0.1uF
C81 "B32652A3684J" B32652_1800x900x1750 131,28.5 r180 top locked value=0.68uF
C82 "" 0402L 15.25,104 r270 bottom value=0.1uF
C83 "GRM188R71E474KA12D" 0603L 81.25,103.25 r270 bottom value=0.47uF
C84 "C0603C104K5RACTU" 0603L 63.75,94.5 r270 bottom value=0.1uF
C85 "+" SM_RADIAL_B 68.125,100.625 r180 bottom value=10uF
C86 "+" SM_RADIAL_C 69,123 r90 bottom value=100uF
C87 "GRM188R61A106ME69D" 0603L 44,100.75 r0 top value=10uF
C88 "GRM155R71A104KA01D" 0402L 42.25,101.25 r270 top value=0.1uF
C89 "GRM155R71A104KA01D" 0402L 47.75,101.25 r90 top value=0.1uF
C90 "GRM155R71A104KA01D" 0402L 43.25,95.25 r180 bottom value=0.1uF
C91 "GRM188R61A106ME69D" 0603L 28.125,101.25 r90 bottom value=10uF
C92 "GRM21BZ71A226ME15L" 0805_KTR 20.625,104 r270 bottom value=22uF
C93 "GRM188R61A106ME69D" 0603L 46,108 r0 bottom value=10uF
C94 "GRM155R71A104KA01D" 0402L 45.75,106.75 r180 bottom value=0.1uF
C95 "GRM188R71C105KA12D" 0603L 25.75,106.25 r270 bottom value=1uF
C96 "C0603C104K5RACTU" 0603L 81.5,15.75 r180 bottom value=0.1uF
C97 "GRM31CR72A105KA01L" 1206_180L 86,14 r0 bottom value=1uF
C98 "DNP" 1206_180L 141.25,106 r0 bottom value=1uF
C99 "GRM155R71C104KA88D" 0402L 3.625,114.75 r0 top value=0.1uF
C100 "GRM155R71C104KA88D" 0402L 3.6,112.5 r0 top value=0.1uF
C101 "GRM155R71C104KA88D" 0402L 18.875,112.75 r180 top value=0.1uF
C102 "GRM155R71C104KA88D" 0402L 3.625,118.75 r0 top value=0.1uF
C103 "DNP" 1206_180L 141.25,90 r0 bottom value=1uF
C104 "DNP" 1206_180L 141.25,36.25 r0 bottom value=1uF
C105 "DNP" 1206_180L 141.25,19 r0 bottom value=1uF
C106 "GRM1555C1H102JA01D" 0402L 61.375,69.5 r180 bottom value=1000pF
C107 "GRM188R71C105KA12D" 0603L 74.625,71.875 r90 top value=1uF
C108 "GRM155R71A104KA01D" 0402L 23,48.25 r180 bottom value=0.1uF
C109 "GRM155R71A104KA01D" 0402L 35.25,50.25 r90 bottom value=0.1uF
C110 "GRM155R71A104KA01D" 0402L 34.75,53.75 r90 bottom value=0.1uF
C111 "GRM155R71A104KA01D" 0402L 34.75,58.75 r90 bottom value=0.1uF
C112 "GRM155R71A104KA01D" 0402L 34.75,61.5 r90 bottom value=0.1uF
C113 "GRM155R71A104KA01D" 0402L 34.75,64 r90 bottom value=0.1uF
C114 "GRM155R71A104KA01D" 0402L 43.875,60 r0 bottom value=0.1uF
C115 "GRM155R71A104KA01D" 0402L 43.875,62.75 r0 bottom value=0.1uF
C116 "GRM155R71A104KA01D" 0402L 43.875,57.5 r0 bottom value=0.1uF
C117 "GRM155R71A104KA01D" 0402L 43.875,55 r0 bottom value=0.1uF
C118 "GRM155R71A104KA01D" 0402L 51.375,88.75 r0 top value=0.1uF
C119 "GRM155R71A104KA01D" 0402L 51.875,92 r0 top value=0.1uF
C120 "GRM155R71A104KA01D" 0402L 10.875,32 r0 bottom value=0.1uF
C121 "GRM155R71A104KA01D" 0402L 28.625,88.25 r270 bottom value=0.1uF
C122 "GRM155R71A104KA01D" 0402L 55.375,85.25 r270 bottom value=0.1uF
C123 "GRM155R71A104KA01D" 0402L 34,87.75 r270 bottom value=0.1uF
C124 "GRM21BZ71A226ME15L" 0805_KTR 30,112 r180 bottom value=22uF
C125 "GRM21BZ71A226ME15L" 0805_KTR 27.125,110.125 r0 bottom value=22uF
C126 "GRM155R71C104KA88D" 0402L 26.625,111.375 r0 bottom value=0.1uF
C127 "GRM155R71C104KA88D" 0402L 18.375,116.25 r90 top value=0.1uF
C128 "GRM155R71C104KA88D" 0402L 3.625,111.5 r0 top value=0.1uF
C129 "GRM155R71C104KA88D" 0402L 3.625,113.625 r0 top value=0.1uF
C130 "GRM155R71C104KA88D" 0402L 3.625,116.75 r0 top value=0.1uF
C131 "GRM155R71C104KA88D" 0402L 14.25,118.75 r90 top value=0.1uF
C132 "GRM155R71C104KA88D" 0402L 15.875,118.75 r90 top value=0.1uF
C133 "GRM155R71C104KA88D" 0402L 11.5,118.75 r90 top value=0.1uF
C134 "GRM155R71C104KA88D" 0402L 7.875,121.375 r270 top value=0.1uF
C135 "GRM155R71C104KA88D" 0402L 5.875,121.375 r270 top value=0.1uF
C136 "GRM155R71C104KA88D" 0402L 18.875,113.625 r180 top value=0.1uF
C137 "GRM155R71C104KA88D" 0402L 18.375,110.625 r90 top value=0.1uF
C138 "GRM155R71C104KA88D" 0402L 16,106.5 r180 top value=0.1uF
C139 "GRM155R71C104KA88D" 0402L 7.75,106.5 r0 top value=0.1uF
C140 "GRM155R71C104KA88D" 0402L 5.875,108.625 r270 top value=0.1uF
C141 "GRM155R71C104KA88D" 0402L 9.375,123.5 r180 bottom value=0.1uF
C142 "GRM188R71A225KE15D" 0603L 12.75,125.55 r0 bottom value=2.2uF
C143 "GRM155R71C104KA88D" 0402L 3.875,101.875 r0 bottom value=0.1uF
C144 "GRM155R71C104KA88D" 0402L 6.5,103.75 r180 top value=0.1uF
C145 "GRM155R71C104KA88D" 0402L 10.125,101.75 r0 bottom value=0.1uF
C146 "GRM155R71C104KA88D" 0402L 6.5,102.875 r180 top value=0.1uF
C147 "GRM155R71C104KA88D" 0402L 8.125,101.75 r180 bottom value=0.1uF
C148 "GRM155R71C104KA88D" 0402L 11.625,83.5 r90 bottom value=0.1uF
C149 "GRM155R71C104KA88D" 0402L 6.25,85.625 r0 bottom value=0.1uF
C150 "GRM1555C1E471JA01D" 0402L 10,85.625 r270 bottom value=470pF
C151 "GRM155R71A104KA01D" 0402L 71.375,7.5 r90 bottom value=0.1uF
C152 "DNP" 1206L 148.75,98 r0 bottom value=1000pF
C153 "DNP" 1206L 148.75,95 r0 bottom value=1000pF
C154 "DNP" 1206L 148.75,29.5 r0 bottom value=1000pF
C155 "DNP" 1206L 148.75,26.75 r0 bottom value=1000pF
C156 "GRM155R71A104KA01D" 0402L 41.75,90.25 r180 bottom value=0.1uF
D1 "USB RDY" LTST-C170TBKT_Blue 23.75,114 r180 top value=Blue
D2 "SPDIF-LOCK" "LB Q39G_BLUE" 31,113.75 r180 top value=Blue
D3 "SPDIF-READY" LED_LTST-C171 37,114 r180 top value=Green
D4 "MUTE" LED_LTST-C190_Red 42,20 r180 top value=Red
D5 "P2" "LB Q39G_BLUE" 48.75,10 r180 top value=Blue
D6 "P1" "LB Q39G_BLUE" 53.75,10 r180 top value=Blue
D7 "P0" "LB Q39G_BLUE" 58.75,10 r180 top value=Blue
D8 "USB" "LB Q39G_BLUE" 42,28 r180 top value=Blue
D9 "CLIP_OTW" LTST-C170KFKT_Orange 104,21.25 r180 top value=Orange
D10 "FAULT" LED_LTST-C170_Red 104,16.25 r180 top value=Red
D11 "SK310A-TP" SMA 105,107.5 r0 bottom value=100V
D12 "B1100-13-F" SMA 98.75,99.25 r180 bottom value=100V
D13 "12V" LED_LTST-C171 68,127 r180 top value=Green
D14 "3.3V" LED_LTST-C171 68,122 r180 top value=Green
D15 "OPTICAL" "LB Q39G_BLUE" 48,28 r180 top value=Blue
D16 "COAX" "LB Q39G_BLUE" 55.25,28 r180 top value=Blue
D17 "B1100-13-F" SMA 28.75,121.5 r90 bottom value=100V
FID1 "Fiducial" Fiducial10-20 8.75,3.75 r0 top
FID2 "Fiducial" Fiducial10-20 151.25,3.75 r0 top
FID3 "Fiducial" Fiducial10-20 151.25,126.25 r0 top
FID4 "Fiducial" Fiducial10-20 8.75,3.75 r180 bottom
FID5 "Fiducial" Fiducial10-20 151.25,3.75 r180 bottom
FID6 "Fiducial" Fiducial10-20 151.25,126.25 r180 bottom
H1 "ATS078036036-TI1OP-1099-C1-R1" Advanced_ATS078036036-TI1OP-1099-C1-R1 82,65.625 r90 top locked
H2 "M3x8mm" "APM_RM3X8MM 2701" 4,4 r0 top
H3 "M3x8mm" "APM_RM3X8MM 2701" 4,126 r0 top locked
H4 "M3x8mm" "APM_RM3X8MM 2701" 156,126 r0 top
H5 "M3x8mm" "APM_RM3X8MM 2701" 156,4 r0 top
H6 "M3x25mm" Keystone24438 156,4 r180 bottom
H7 "M3x25mm" Keystone24438 156,126 r180 bottom
H8 "M3x25mm" Keystone24438 4,126 r180 bottom
H9 "M3x25mm" Keystone24438 4,4 r180 bottom
H10 "M3x8mm" "APM_RM3X8MM 2701" 156,62.5 r0 top
H11 "M3x25mm" Keystone24438 156,62.5 r180 bottom
J1 "MCLK-SEL" Sullins_PBC02SAAN 47.5,76.25 r90 top
J2 "FREQ SEL" Sullins_PBC02SAAN 47.5,85 r270 top
J3 "" PBC03SAAN 27.5,69 r0 top
J4 "" PBC03SAAN 27.5,63 r0 top
J5 "SPDIF-IN" Keystone_971 40,126 r270 top locked
J6 "" PBC03SAAN 27.5,57 r0 top
J7 "" PBC03SAAN 27.5,51 r0 top
J8 "5V SEL" PBC03SAAN 28.75,126.25 r0 bottom
J9 "I2X" CONN_SBH11-PBPC-D07-ST-BK 38.5,60 r270 top locked
J10 "OUTA" Pomona_6883 150,96.5 r90 top locked
J11 "JTAG POWER" Sullins_PBC02SAAN 12.5,7.125 r0 top
J12 "JTAG" Mill-Max_851-XX-006-10-001000 20,7.75 r90 top
J13 "GNDA" Keystone_7007 150,70.5 r0 top locked
J14 "MODE" Sullins_PBC02SAAN 58,18.98 r0 top
J15 "OUTB" Pomona_6883 150,28.5 r90 top locked
J16 "HS-EN" Sullins_PBC02SAAN 22.5,125 r180 top
J17 "JTAG" SULLINS_LPPB061NGCN-RC 1.5,90 r270 top
J18 "USB" CONN_USB_DX4R205JJA 12.5,130 r180 top locked
J19 "ADR" Sullins_PBC02SAAN 65,19 r0 top
J20 "GVDD" Sullins_PBC02SAAN 60,93.75 r270 bottom
J21 "GNDB" Keystone_7007 150,55.5 r0 top locked
J22 "PEC04DAAN" CONN_PEC04DAAN 90,7 r270 top
J23 "0022112042" CONN_22112042 69,52 r180 bottom locked
J24 "PVDD" Pomona_6883 92,121 r0 top locked
J25 "S1911-46R" HARWIN_S1911-46R 86.75,106.75 r180 bottom
J26 "PVDD-IN" Sullins_PBC02SAAN 108.25,103.25 r90 bottom
J27 "12V" Sullins_PBC02SAAN 67.5,93.75 r90 bottom
J28 "SSW-114-01-G-D" CONN_SSW-114-01-G-D 12,60 r90 top locked
J29 "3.3V" Sullins_PBC02SAAN 69,116 r0 bottom
J30 "J9 DATA SEL" PBC03SAAN 27.5,77.5 r0 top
J31 "INB+" Sullins_PBC02SAAN 58,44 r90 top
J32 "INB-" Sullins_PBC02SAAN 58,40 r90 top
J33 "" Sullins_PBC02SAAN 17.5,93.75 r0 top locked
J34 "PBC02SAAN" Sullins_PBC02SAAN 4,60 r0 top
J35 "SLAVE ENABLE" Sullins_PBC02SAAN 5,17.5 r0 top
J36 "JTAG-RA" SULLINS_LPPB061NGCN-RC 28,1.5 r0 top
J37 "I2S SELECT" Sullins_PBC02SAAN 26.25,40 r90 top
L1 "VLS2012ET-R47N" VLS2012ET 29.4,114.25 r180 bottom value=470nH
L2 "MPZ2012S601A" 0805_KTR 17.5,125.75 r0 bottom value="600 ohm"
L3 "VLCF4020T-2R2N1R7" VLCF4020 70,108.875 r180 bottom value=2.2uH
L4 "MMZ1005Y121C" 0402L 40,123.5 r270 bottom value="120 ohm"
L5 "MA5173" MA5173 126,110.5 r90 top locked value=7uH
L6 "MA5173" MA5173 126,70.5 r90 top locked value=7uH
L7 "MA5173" MA5173 126,54.5 r270 top locked value=7uH
L8 "MA5173" MA5173 126,14.5 r270 top locked value=7uH
L9 "7447714101" WE-PD_1050 90,99.25 r90 bottom value=100uH
Logo1 "Texas Instruments" TI_Stacked_Overlay_Small 139.5,3.25 r0 top
Logo2 "Pb-Free Symbol" Pb-Free_Overlay_Medium 23.875,19.375 r0 top
Logo3 "FCC disclaimer" FCC_disclaimer 82,24.5 r0 top
Q1 "MMBT2222A" SOT-23 54.5,34 r270 bottom value="40 V"
Q2 "MMBT2222A" SOT-23 40,25 r270 bottom value="40 V"
Q3 "MMBT2222A" SOT-23 46,16 r270 bottom value="40 V"
Q4 "MMBT2222A" SOT-23 50,16 r270 bottom value="40 V"
Q5 "MMBT2222A" SOT-23 54,15.75 r270 bottom value="40 V"
Q6 "MMBT2222A" SOT-23 41.25,34 r270 bottom value="40 V"
Q7 "MMBT2222A" SOT-23 47.25,34 r270 bottom value="40 V"
R1 "ERJ-2RKF4022X" 0402L 29.25,106 r180 bottom value=40.2k
R2 "RC0603FR-071ML" 0603L 29.75,107.5 r180 bottom value=1.00Meg
R3 "RC0603FR-07162KL" 0603L 31.5,106.15 r180 bottom value=162k
R4 "RC0603FR-07100KL" 0603L 70.25,106.125 r0 top value=100k
R5 "RC0201FR-0710KL" 0201L 22.5,27.5 r0 top value=10.0k
R6 "RC0603FR-0733K2L" 0603L 22.5,106.25 r270 bottom value=33.2k
R7 "RC0603FR-0710K7L" 0603L 23.75,106.25 r270 bottom value=10.7k
R8 "RC0603FR-0713K7L" 0603L 22.5,98.75 r90 bottom value=13.7k
R9 "RC0603FR-0711KL" 0603L 23.75,98.75 r90 bottom value=11.0k
R10 "DNP" 0603L 31.25,45 r180 bottom value=0
R11 "DNP" 0603L 35.625,48 r0 bottom value=0
R12 "DNP" 0603L 35.625,46.625 r180 bottom value=0
R13 "RC1206JR-070RL" 1206L 62.5,67 r270 bottom value=0
R14 "" 0805_KTR 62.5,63.375 r270 bottom value=0
R15 "DNP" 0603L 64.875,59.875 r180 bottom value=18.0k
R16 "ERJ-2RKF33R0X" 0402L 53.5,114.75 r270 top value=33.0
R17 "RC0402FR-0749R9L" 0402L 45,64.375 r0 bottom value=49.9
R18 "RC0402FR-0749R9L" 0402L 45,58.75 r0 bottom value=49.9
R19 "RC0603JR-07560RL" 0603L 33.75,115 r180 bottom value=560
R20 "RC0402FR-071KL" 0402L 51,101.5 r180 bottom value=1.00k
R21 "RC0402FR-0749R9L" 0402L 45,56.25 r0 bottom value=49.9
R22 "RC0402FR-074K99L" 0402L 50.25,98.75 r180 bottom value=4.99k
R23 "RC0402FR-071KL" 0402L 38,114 r90 bottom value=1.00k
R24 "RC0402FR-0749R9L" 0402L 45,61.25 r0 bottom value=49.9
R25 "" 0402 50.75,96 r90 bottom value=10.0k
R26 "ERJ-2GE0R00X" 0402L 8.75,53.125 r270 bottom value=0
R27 "ERJ-2GE0R00X" 0402L 8.75,55.75 r270 bottom value=0
R28 "DNP" 0805_KTR 48.75,127.5 r0 bottom value=0
R29 "DNP" 0603L 64,63.25 r270 bottom value=2.00k
R30 "RC1206JR-070RL" 1206L 60.25,67 r270 bottom value=0
R31 "RC0805JR-070RL" 0805_KTR 89.75,78.75 r180 bottom value=0
R32 "RC0603FR-07100KL" 0603L 101.25,78.75 r0 bottom value=100k
R33 "" 0805_KTR 60.25,63.375 r270 bottom value=0
R34 "ERJ-6ENF1823V" 0805_KTR 99,108.75 r180 bottom value=182k
R35 "DNP" 0603L 57.875,59.875 r0 bottom value=18.0k
R36 "RC0805JR-070RL" 0805_KTR 89.75,54.25 r90 top value=0
R37 "DNP" 0603L 58.75,63.25 r270 bottom value=2.00k
R38 "RC0201FR-0725K5L" 0201L 35,28 r0 bottom value=25.5k
R39 "RC0201FR-0725K5L" 0201L 34.25,20 r0 bottom value=25.5k
R40 "RC0201FR-0725K5L" 0201L 34.375,12.5 r0 bottom value=25.5k
R41 "RC0402FR-0747KL" 0402L 22.75,8.5 r0 bottom value=47.0k
R42 "RC0201FR-0725K5L" 0201L 34.25,5 r0 bottom value=25.5k
R43 "RC0402FR-0749R9L" 0402L 11.75,18.125 r270 bottom value=49.9
R44 "RC0201FR-0725K5L" 0201L 55.75,3.75 r0 bottom value=25.5k
R45 "RC0201FR-0725K5L" 0201L 47.5,3.75 r0 bottom value=25.5k
R46 "RC0603JR-07560RL" 0603L 40,21.875 r90 bottom value=560
R47 "RC0603JR-07560RL" 0603L 46,12.5 r90 bottom value=560
R48 "RC0603JR-07560RL" 0603L 50,12.5 r90 bottom value=560
R49 "RC0603JR-07560RL" 0603L 54,12.5 r90 bottom value=560
R50 "RC0603FR-072KL" 0603L 37,26 r180 bottom value=2.00k
R51 "RC0603FR-072KL" 0603L 43,17.25 r180 bottom value=2.00k
R52 "RC0603FR-072KL" 0603L 49,19.125 r90 bottom value=2.00k
R53 "RC0603FR-072KL" 0603L 53,19.125 r90 bottom value=2.00k
R54 "ERJ-3GEY0R00V" 0603L 5,41 r270 bottom value=0
R55 "ERJ-3GEY0R00V" 0603L 3,41 r270 bottom value=0
R56 "RC0603FR-078K06L" 0603L 93.75,78.75 r180 bottom value=8.06k
R57 "RC0603JR-07560RL" 0603L 41.25,30.875 r90 bottom value=560
R58 "RC0402FR-074K99L" 0402L 92,105.5 r180 bottom value=4.99k
R59 "RC0603FR-07100KL" 0603L 63.25,71.25 r270 bottom value=100k
R60 "RC0603FR-073K3L" 0603L 89.5,14 r180 bottom value=3.30k
R61 "RC1206JR-070RL" 1206L 70.875,73.75 r180 bottom value=0
R62 "ERJ-3GEY0R00V" 0603L 23.75,28.75 r180 bottom value=0
R63 "DNP" 0603L 31.95,109.45 r270 bottom value=0
R64 "RC0603FR-07100KL" 0603L 59.5,71.25 r270 bottom value=100k
R65 "RC0603FR-07100KL" 0603L 75.125,74.5 r180 bottom value=100k
R66 "RC0201FR-0710KL" 0201L 18.125,27.875 r0 bottom value=10.0k
R67 "RC0603FR-07499RL" 0603L 62,71.25 r270 bottom value=499
R68 "" 0805_KTR 67.25,69 r270 bottom value=0
R69 "RC0603FR-07499RL" 0603L 60.75,71.25 r270 bottom value=499
R70 "DNP" 0603L 64.875,65.5 r0 bottom value=18.0k
R71 "DNP" 0603L 65.75,68.875 r270 bottom value=2.00k
R72 "RC1206JR-070RL" 1206L 70.875,71.5 r180 bottom value=0
R73 "" 0805_KTR 69.5,69 r270 bottom value=0
R74 "RC0603FR-0722KL" 0603L 81.125,64.625 r180 bottom value=22.0k
R75 "RC0603FR-0730KL" 0603L 94,3.25 r180 bottom value=30.0k
R76 "RC0603FR-0720KL" 0603L 94,5.75 r180 bottom value=20.0k
R77 "RC0201FR-0710KL" 0201L 94,8.25 r180 bottom value=10.0k
R78 "RC0603JR-07560RL" 0603L 104.5,21.25 r180 bottom value=560
R79 "RC0603JR-07560RL" 0603L 104.5,16.25 r180 bottom value=560
R80 "ERJ-2RKF1002X" 0402L 19.25,94.5 r90 bottom value=10.0k
R81 "RC0402FR-074K99L" 0402L 34.5,85.5 r180 bottom value=4.99k
R82 "RC0402FR-074K99L" 0402L 41.75,90.25 r180 top value=4.99k
R83 "RC0201FR-0733R2L" 0201 20.75,110.5 r180 bottom value=33.2
R84 "RC0402FR-071KL" 0402L 94,107.25 r270 bottom value=1.00k
R85 "RC0603FR-071K5L" 0603L 64,127 r180 bottom value=1.50k
R86 "RC0603FR-07499RL" 0603L 62.75,122 r180 bottom value=499
R87 "DNP" 1206L 136.25,106 r0 bottom value=3.30
R88 "RC0603FR-07100KL" 0603L 75.125,70.75 r180 bottom value=100k
R89 "DNP" 1206L 136.25,90 r0 bottom value=3.30
R90 "RC0201FR-0710KL" 0201L 58,15.625 r90 bottom value=10.0k
R91 "RC0201FR-0710KL" 0201L 65,15.625 r90 bottom value=10.0k
R92 "ERJ-2RKF1002X" 0402L 28.75,16.25 r270 bottom value=10.0k
R93 "DNP" 1206L 136.25,36.25 r0 bottom value=3.30
R94 "DNP" 1206L 136.25,19 r0 bottom value=3.30
R95 "RC0603FR-07499RL" 0603L 75.125,73.25 r180 bottom value=499
R96 "DNP" 0603L 71.875,65.5 r180 bottom value=18.0k
R97 "DNP" 0603L 71,68.875 r270 bottom value=2.00k
R98 "RC0603FR-07499RL" 0603L 75.125,72 r180 bottom value=499
R99 "ERJ-3GEY0R00V" 0603L 54,44 r0 bottom value=0
R100 "ERJ-3GEY0R00V" 0603L 54,40 r0 bottom value=0
R101 "DNP" 0603L 77.875,67.25 r270 bottom value=0
R102 "ERJ-3GEY0R00V" 0603L 77.875,64.625 r90 bottom value=0
R103 "ERJ-3GEY0R00V" 0603L 72,36 r0 bottom value=0
R104 "ERJ-3GEY0R00V" 0603L 86,36 r0 bottom value=0
R105 "RC0603FR-072KL" 0603L 16.25,36.25 r180 bottom value=2.00k
R106 "RC0603JR-07560RL" 0603L 54.5,30.875 r90 bottom value=560
R107 "RC0603FR-072KL" 0603L 16.25,34.75 r180 bottom value=2.00k
R108 "RC0603JR-07560RL" 0603L 47.25,30.875 r90 bottom value=560
R109 "RC0603FR-072KL" 0603L 16.25,33.25 r180 bottom value=2.00k
R110 "RC0402FR-071KL" 0402L 3.625,117.875 r180 top value=1.00k
R111 "ERJ-2GE0R00X" 0402L 22.25,40 r180 bottom value=0
R112 "ERJ-3GEY0R00V" 0603L 30,48 r0 bottom value=0
R113 "ERJ-3GEY0R00V" 0603L 33,48 r180 bottom value=0
R114 "RC0201FR-0710KL" 0201L 8.75,32 r180 bottom value=10.0k
R115 "RC0402FR-07100KL" 0402L 41.5,64.5 r270 bottom value=100k
R116 "RC0402FR-07100KL" 0402L 41.5,58.25 r90 bottom value=100k
R117 "RC0402FR-07100KL" 0402L 41.5,55.75 r90 bottom value=100k
R118 "RC0402FR-07100KL" 0402L 41.5,61.75 r270 bottom value=100k
R119 "DNP" 0402L 54.25,99.25 r270 top value=10.0k
R120 "DNP" 0402L 51.625,101.875 r90 top value=10.0k
R121 "ERJ-2RKF1002X" 0402L 53.25,99.25 r270 top value=10.0k
R122 "DNP" 0402L 50.75,101.875 r90 top value=10.0k
R123 "RMCF0402FT10K0" 0402L 15.25,46 r0 bottom value=10.0k
R124 "RC0402FR-074K99L" 0402L 30.625,90 r90 bottom value=4.99k
R125 "RC0805JR-070RL" 0805_KTR 66.25,83.75 r180 bottom value=0
R126 "RC0805JR-070RL" 0805_KTR 62.5,85 r180 bottom value=0
R127 "RC0805JR-070RL" 0805_KTR 16.25,43.5 r180 bottom value=0
R128 "RC0805JR-070RL" 0805_KTR 10.75,41 r90 bottom value=0
R129 "RC0201FR-0710KL" 0201L 8.25,31 r90 top value=10.0k
R130 "ERJ-3GEY0R00V" 0603L 47.875,89 r180 bottom value=0
R131 "ERJ-3GEY0R00V" 0603L 47.875,92 r180 bottom value=0
R132 "ERJ-3GEY0R00V" 0603L 47.25,94.5 r90 bottom value=0
R133 "RC0402FR-074K99L" 0402L 32.875,90 r90 bottom value=4.99k
R134 "ERJ-3GEY0R00V" 0603L 10,91.25 r0 bottom value=0
R135 "ERJ-3GEY0R00V" 0603L 10,88.75 r0 bottom value=0
R136 "RC0201FR-0747KL" 0201L 20.75,119.25 r0 bottom value=47.0k
R137 "RC0201FR-0747KL" 0201L 20.75,118.5 r0 bottom value=47.0k
R138 "RC0201FR-0747KL" 0201L 20.75,117.75 r0 bottom value=47.0k
R139 "RC0201FR-0747KL" 0201L 20.75,117 r0 bottom value=47.0k
R140 "RC0603FR-074R75L" 0603L 17,104.25 r180 bottom value=4.75
R141 "RC0603JR-07560RL" 0603L 22.75,115.25 r0 bottom value=560
R142 "RC0201FR-0733R2L" 0201 20.625,121.875 r180 bottom value=33.2
R143 "RC0201FR-0733R2L" 0201 20.625,120.375 r180 bottom value=33.2
R144 "RC0201FR-0710KL" 0201L 18.5,123.75 r270 bottom value=10.0k
R145 "ERJ-2RKF1002X" 0402L 9.375,124.375 r180 bottom value=10.0k
R146 "RC0201FR-0733R2L" 0201 2.125,106.25 r90 bottom value=33.2
R147 "ERJ-1GE0R00C" 0201L 13.125,101.92 r270 bottom value=0
R148 "RC0201FR-0743R2L" 0201L 11,123.75 r270 bottom value=43.2
R149 "RC0201FR-0710KL" 0201L 5.625,91.875 r180 bottom value=10.0k
R150 "RC0201FR-0710KL" 0201L 13.75,101 r180 bottom value=10.0k
R151 "RC0201FR-0733R2L" 0201 12,92.75 r180 bottom value=33.2
R152 "RC0201FR-0733R2L" 0201 3.75,97.75 r0 bottom value=33.2
R153 "RC0201FR-0733R2L" 0201 5.875,104.625 r0 bottom value=33.2
R154 "RC0201FR-0710KL" 0201L 11.875,98.75 r180 bottom value=10.0k
R155 "RC0201FR-0710KL" 0201L 8.125,84.25 r0 bottom value=10.0k
R156 "RC0201FR-0725K5L" 0201 8.125,83.25 r0 bottom value=25.5k
R157 "RC0402FR-0747KL" 0402L 14.7,123.75 r90 top value=47.0k
R158 "RC0201FR-0751KL" 0201 8.125,82.25 r180 bottom value=51.0k
R159 "RC0805JR-070RL" 0805_KTR 17.5,100.625 r270 bottom value=0
R160 "DNP" 0201L 20.75,112 r180 bottom value=0
R161 "DNP" 0201L 20.75,111.25 r180 bottom value=0
R162 "DNP" 0201L 13.375,103.545 r180 bottom value=0
R163 "DNP" 0201L 13.375,102.92 r180 bottom value=0
R164 "RC0805JR-070RL" 0805_KTR 16.625,98.125 r180 bottom value=0
R165 "ERJ-3GEY0R00V" 0603L 88.375,74.5 r90 bottom value=0
R166 "DNP" 0603L 87.75,72.625 r0 bottom value=0
R167 "DNP" 0603L 15.625,100.625 r270 bottom value=0
R168 "ERJ-3GEY0R00V" 0603L 35,45 r0 bottom value=0
R169 "ERJ-3GEY0R00V" 0603L 38.5,90 r90 bottom value=0
R170 "ERJ-3GEY0R00V" 0603L 36.25,90 r90 bottom value=0
S1 "DAC MUTE" SW_200USP1T1A1M2 74,8 r0 top
S2 "SPDIF-RESET" SW_TL1015AF160QG 48,114.5 r0 top
S3 "AMP RESET" SW_200USP1T1A1M2 82,8 r0 top
S4 "MUTE" SW_TL1015AF160QG 36.25,20 r180 top
S5 "VOL UP" SW_TL1015AF160QG 36.25,12.5 r180 top
S6 "VOL DN" SW_TL1015AF160QG 36.25,5 r180 top
S7 "PROGRAM SEL" SW_TL1015AF160QG 57,3.75 r180 top
S8 "LOAD" SW_TL1015AF160QG 48.75,3.75 r180 top
S9 "INPUT" SW_TL1015AF160QG 36.25,28 r180 top
SH1 "SNT-100-BK-G" SNT-100-BK-G#1 69,116 r90 bottom value=1x2
SH2 "SNT-100-BK-G" SNT-100-BK-G#1 30,126.25 r180 bottom value=1x2
SH3 "SNT-100-BK-G" SNT-100-BK-G#1 60,93.75 r180 bottom value=1x2
SH4 "SNT-100-BK-G" SNT-100-BK-G#1 108.25,103.25 r180 bottom value=1x2
SH5 "SNT-100-BK-G" SNT-100-BK-G#1 67.5,93.75 r180 bottom value=1x2
SH6 "SNT-100-BK-G" SNT-100-BK-G#2 22.5,125 r90 top value=1x2
SH7 "SNT-100-BK-G" SNT-100-BK-G#2 47.5,76.25 r0 top value=1x2
SH8 "SNT-100-BK-G" SNT-100-BK-G#2 26.25,63 r0 top value=1x2
SH9 "SNT-100-BK-G" SNT-100-BK-G#2 26.25,51 r0 top value=1x2
SH10 "SNT-100-BK-G" SNT-100-BK-G#2 48.75,86.25 r270 top value=1x2
SH11 "SNT-100-BK-G" SNT-100-BK-G#2 26.25,69 r0 top value=1x2
SH12 "SNT-100-BK-G" SNT-100-BK-G#2 26.25,57 r0 top value=1x2
SH13 "SNT-100-BK-G" SNT-100-BK-G#2 59.25,45.25 r90 top value=1x2
SH14 "SNT-100-BK-G" SNT-100-BK-G#2 59.25,38.75 r90 top value=1x2
SH15 "SNT-100-BK-G" SNT-100-BK-G#2 11.25,8.5 r0 top value=1x2
SH16 "SNT-100-BK-G" SNT-100-BK-G#2 16.25,95 r0 top value=1x2
SH17 "SNT-100-BK-G" SNT-100-BK-G#2 3.75,18.75 r0 top value=1x2
SH18 "SNT-100-BK-G" SNT-100-BK-G#2 90,8.25 r0 top value=1x2
SH19 "SNT-100-BK-G" SNT-100-BK-G#2 26.25,40 r0 top value=1x2
SH20 "SNT-100-BK-G" SNT-100-BK-G#2 26.25,77.5 r0 top value=1x2
SH21 "SNT-100-BK-G" SNT-100-BK-G#2 58,19 r90 top value=1x2
SH22 "SNT-100-BK-G" SNT-100-BK-G#2 65,19 r90 top value=1x2
TP1 "SDIN" Keystone5003 48.75,63.75 r0 top
TP2 "MCLK" Keystone5003 48.75,70 r0 top
TP3 "BCLK" Keystone5003 48.75,57.5 r0 top
TP4 "LRCK" Keystone5003 48.75,51.25 r0 top
TP5 "5V-IN" Keystone5010 32.5,102.5 r0 top
TP6 "GND" Keystone5011 32.5,97.5 r0 top locked
TP7 "PVDD_B" Keystone5128 106,76 r180 bottom
TP8 "PVDD_A" Keystone5128 106,49 r180 bottom
TP9 "GVDD_A" TP_H045P075 75.625,67 r90 bottom
TP10 "GVDD_B" TP_H045P075 89.75,56 r90 bottom
TP11 "AVDD" TP_H045P075 74.75,60 r90 bottom
TP12 "DAC-AVDD" TP_H045P075 89.5,76.5 r90 bottom
TP13 "DVDD" TP_H045P075 75.375,61.5 r90 bottom
TP14 "OC-ADJ" TP_H045P075 79.25,64.625 r90 bottom
TP15 "CLIP_OTW" Keystone5128 98.5,21.25 r90 top
TP16 "FAULT" Keystone5128 98.5,16.25 r90 top
TP17 "OUTA+" Keystone5003 108.75,70 r0 top
TP18 "OUTA-" Keystone5003 106.25,65 r0 top
TP19 "OUTB+" Keystone5003 106.25,60 r0 top
TP20 "OUTB-" Keystone5003 108.75,55 r0 top
TP21 "SCL" Keystone5003 28.75,85 r90 top
TP22 "SDA" Keystone5003 38.375,85 r90 top
TP23 "GND" Keystone5001 48.75,45.625 r90 top
U1 "TPS62085RLTR" RLT0007A 30,109.75 r90 bottom
U2 "XEF216-512-TQ128-C20" TQFP-128 11.25,113.75 r0 bottom locked
U3 "TCA9406DCUR" DCU0008A_N 31.25,87.5 r180 bottom
U4 "SPDIF-IN" PLR135_T10 56,123 r0 top
U5 "TPS3802K33DCKR" DCK0005A_N 81,14 r0 bottom
U6 "SN74AVC2T244DQMR" DQM0008A 6.5,103.25 r270 bottom
U7 "SRC4392IPFBR" PFB0048A_N 44,101 r270 bottom locked
U8 "TAS3251DKQR" DKQ0056A 82,65.625 r0 top locked
U9 "SN74LVC2G157DCTR" DCT0008A_N 20.5,68 r0 bottom
U10 "LM5010ASD/NOPB" SDC10A 98.125,105 r90 bottom
U11 "SN74LVC2G157DCTR" DCT0008A_N 20.5,62 r0 bottom locked
U12 "MSP430G2955IRHA40R" RHA0040B 12.5,27.5 r0 bottom
U13 "SN74LVC2G157DCTR" DCT0008A_N 20.5,56 r0 bottom
U14 "SN74LVC2G157DCTR" DCT0008A_N 20.5,50 r0 bottom
U15 "LM2940IMP-12/NOPB" MP04A_N 77,107.75 r90 bottom
U16 "TPS62163DSGR" DSG0008A 70,105 r90 bottom
U17 "TPS7A8801RTJR" RTJ0020D 25,102.5 r180 bottom locked
U18 "LVC1G125DSF" DSF0006A 33.5,64.75 r0 bottom
U19 "LVC1G125DSF" DSF0006A 43,64 r0 bottom
U20 "LVC1G125DSF" DSF0006A 33.5,59.5 r0 bottom
U21 "LVC1G125DSF" DSF0006A 43,58.75 r0 bottom
U22 "LVC1G125DSF" DSF0006A 33.5,54.5 r0 bottom
U23 "LVC1G125DSF" DSF0006A 43,56.25 r0 bottom
U24 "LVC1G125DSF" DSF0006A 33.5,62.25 r0 bottom
U25 "LVC1G125DSF" DSF0006A 43,61.25 r0 bottom
U26 "CDCE913PWR" PW0014A_N 8.25,97.5 r270 bottom locked
U27 "LVC1G14" DRL0005A 53.625,85.25 r0 bottom
U28 "LVC1G14" DRL0005A 33.75,50 r90 bottom
U29 "SN74LVC2G07DSFR" DSF0006A 8.125,85.625 r180 bottom
U30 "TPS3897ADRYR" DRY0006A 10,83.75 r90 bottom
U31 "SN74LVC2G157DCTR" DCT0008A_N 43.125,88 r180 bottom
Y1 "ASTMLPA-24.000MHZ-EJ-E-T" Abracon_ASTMLPA 3.75,103.75 r0 bottom
Y2 "ASTMHTA-24.576MHZ-AJ-E" Abracon_ASTMLPA 50.875,88.25 r90 bottom
Y3 "TD-22.5792MBD-T" TXC_TD 51.125,91.25 r90 bottom
ZZ1 "These assemblies are ESD sensitive, ESD precautions shall be observed." AssemblyNote 5,145 r0 top
ZZ2 "These assemblies must be clean and free from flux and all contaminants. Use of no clean flux is not acceptable." AssemblyNote 5,143 r0 top
ZZ3 "These assemblies must comply with workmanship standards IPC-A-610 Class 2, unless otherwise specified." AssemblyNote 5,141 r0 top

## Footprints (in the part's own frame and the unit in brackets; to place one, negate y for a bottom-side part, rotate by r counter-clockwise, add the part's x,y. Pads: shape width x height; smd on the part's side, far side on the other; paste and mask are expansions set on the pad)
0201 [mm] "Data from Kemet datasheet CC101_COM dated 7/28/11"
  rect 0.46x0.42 smd mask+0.048: 1(-0.33,0) 2(0.33,0)
  body extent -0.31,-0.16 0.31,0.16, height 0.26
0201L [mm] "Data from Kemet datasheet CC101_COM dated 7/28/11"
  rect 0.36x0.32 smd mask+0.048: 1(-0.28,0) 2(0.28,0)
  body extent -0.31,-0.16 0.31,0.16, height 0.26
0402 [mm] "0402 from SM-752 data"
  rect 0.8x0.6 smd: 1(-0.6,0) 2(0.6,0)
  silkscreen extent -1.22,-0.52 1.22,0.52, body extent -0.55,-0.3 0.55,0.3, height 0.6
0402L [mm] "0402 from SM-752 data"
  rect 0.6x0.5 smd: 1(-0.5,0) 2(0.5,0)
  body extent -0.55,-0.3 0.55,0.3, height 0.6
0603L [mm] "0603 from SM-752 data"
  rect 0.8x0.85 smd: 1(-0.7,0) 2(0.7,0)
  silkscreen extent -0.07,-0.33 0.07,0.33, body extent -0.87,-0.47 0.87,0.47, height 1
0805_KTR [mm] "ROHM"
  rect 0.7x1.15 smd: 1(-0.95,0) 2(0.95,0)
  silkscreen extent -0.35,-0.7 0.35,0.7, body extent -1.05,-0.67 1.05,0.67, height 0.65
1206_180L [mm] "1206_180"
  rect 1.1x1.75 smd: 1(-1.35,0) 2(1.35,0)
  silkscreen extent -0.4,-0.77 0.4,0.77, body extent -1.75,-0.95 1.75,0.95, height 1.8
1206L [mm] "1206 from SM-752 data"
  rect 1.1x1.75 smd: 1(-1.35,0) 2(1.35,0)
  silkscreen extent -0.4,-0.77 0.4,0.77, body extent -1.7,-0.9 1.7,0.9, height 1.35
1210_210L [mm] "1210"
  rect 1.1x2.6 smd: 1(-1.35,0) 2(1.35,0)
  silkscreen extent -0.4,-1.2 0.4,1.2, body extent -1.7,-1.35 1.7,1.35, height 2.1
Abracon_ASTMLPA [mm] "SMD, 4-Leads, Body 2x1.6mm"
  rect 0.8x0.9 smd: 1(-0.6,0.75) 2(-0.6,-0.75) 3(0.6,-0.75) 4(0.6,0.75)
  silkscreen extent -1.46,0.74 -1.34,0.86, body extent -0.8,-1 0.8,1, height 0.75
Advanced_ATS078036036-TI1OP-1099-C1-R1 [mm] "Heat Sink, Body 36x78mm"
  round 4.875 hole 3.25: 1(-18.4,0) 2(18.4,0)
  body extent -39,-18 39,18, height 36.5
"APM_RM3X8MM 2701" [mm] "Screw, Dia 6.7mm, Length 8mm, TH"
  round 5.5 hole 3.6: ""(0,0)
  silkscreen extent -3.35,-3.35 3.35,3.35, body extent -3.32,-3.34 3.35,3.34, height 2.38
AssemblyNote [mm] "Assembly Note"
B32652_1800x900x1750 [mm] "TH, 2-Leads, Body 18x9mm, Pin Spacing 15mm"
  round 1.55 hole 1.05: 1(-7.5,0) 2(7.5,0)
  silkscreen extent -9,-4.5 9,4.5, body extent -9,-4.5 9,4.5, height 16.5
CONN_22112042 [mm] "Molex"
  rect 1.65x1.65 hole 1.016 mask+0: 1(-3.81,0)
  round 1.65 hole 1.016 mask+0: 2(-1.27,0) 3(1.27,0) 4(3.81,0)
  silkscreen extent -5.08,-3.25 5.08,3.1, body extent -5,-3.25 5,3.1, height 10.68
CONN_PEC04DAAN [mm] "SULLINS"
  rect 1.65x1.65 hole 1.016 mask+0: 1(-3.81,-1.27)
  round 1.65 hole 1.016 mask+0: 2(-3.81,1.27) 3(-1.27,-1.27) 4(-1.27,1.27) 5(1.27,-1.27) 6(1.27,1.27) 7(3.81,-1.27) 8(3.81,1.27)
  silkscreen extent -6.18,-2.6 5.08,2.54, body extent -5.08,-2.54 5.08,2.54, height 8.38
CONN_SBH11-PBPC-D07-ST-BK [mm] "Sullins recommended land pattern"
  rect 1.65x1.65 hole 1.016 mask+0: 1(-7.62,-1.27)
  round 1.65 hole 1.016 mask+0: 2(-7.62,1.27) 3(-5.08,-1.27) 4(-5.08,1.27) 5(-2.54,-1.27) 6(-2.54,1.27) 7(0,-1.27) 8(0,1.27) 9(2.54,-1.27) 10(2.54,1.27) 11(5.08,-1.27) 12(5.08,1.27) 13(7.62,-1.27) 14(7.62,1.27)
  silkscreen extent -12.64,-5.08 12.64,4.7, body extent -12.64,-4.4 12.64,4.7, height 9.12
CONN_SSW-114-01-G-D [mm] "SAMTEC"
  rect 1.6x1.6 hole 1.04: 1(16.51,-1.27)
  round 1.6 hole 1.04: 2(16.51,1.27) 3(13.97,-1.27) 4(13.97,1.27) 5(11.43,-1.27) 6(11.43,1.27) 7(8.89,-1.27) 8(8.89,1.27) 9(6.35,-1.27) 10(6.35,1.27) 11(3.81,-1.27) 12(3.81,1.27) 13(1.27,-1.27) 14(1.27,1.27) 15(-1.27,-1.27) 16(-1.27,1.27) 17(-3.81,-1.27) 18(-3.81,1.27) 19(-6.35,-1.27) 20(-6.35,1.27) 21(-8.89,-1.27) 22(-8.89,1.27) 23(-11.43,-1.27) 24(-11.43,1.27) 25(-13.97,-1.27) 26(-13.97,1.27) 27(-16.51,-1.27) 28(-16.51,1.27)
  silkscreen extent -17.8,-3.9 17.8,2.5, body extent -17.75,-2.47 17.75,2.47, height 8.55
CONN_USB_DX4R205JJA [mm] "Connecctor, USB-AB, 5 Pos"
  rect 0.4x1.2 smd mask+0.064: 1(-1.3,4.3) 2(-0.65,4.3) 3(0,4.3) 4(0.65,4.3) 5(1.3,4.3)
  oval 1.4x1.2 hole 0.8 slot 1 at 0 deg: 6(-2.5,4.15) 7(2.5,4.15)
  oval 1.2x1.7 hole 0.8 slot 1.3 at 90 deg: 8(-4.1,1.25) 9(4.1,1.25)
  rect 1.73x2.1 smd: M1(-1.96,1.45) M2(1.96,1.45)
  silkscreen extent -3.76,2.4 3.76,4.35, body extent -4.3,-0.65 4.3,4.45, height 2.69
DCK0005A_N [mm] "SOT353, 5-Leads, Body 2x1.3mm, Pitch 0.65mm, Lead Span 2.1mm, IPC Medium Density"
  rrect25% 0.85x0.4 smd: 1(-1.125,0.65) 2(-1.125,0) 3(-1.125,-0.65) 4(1.125,-0.65) 5(1.125,0.65)
  silkscreen extent -1.48,-1.02 0.55,1.1, body extent -1.14,-1 1.14,1, height 0.95
DCT0008A_N [mm] "TSOP, 8-Leads, Body 3x2.8mm, Pitch 0.65mm, IPC Medium Density"
  oval 1.05x0.4 smd: 1(-1.975,0.975) 2(-1.975,0.325) 3(-1.975,-0.325) 4(-1.975,-0.975) 5(1.975,-0.975) 6(1.975,-0.325) 7(1.975,0.325) 8(1.975,0.975)
  silkscreen extent -2.32,-1.57 1.4,1.58, body extent -2.01,-1.47 2.01,1.48, height 1.3
DCU0008A_N [mm] "TSSOP, 8-Leads, Body 2x2.3mm, Pitch 0.5mm, IPC Medium Density"
  oval 0.8x0.3 smd: 1(-1.6,0.75) 2(-1.6,0.25) 3(-1.6,-0.25) 4(-1.6,-0.75) 5(1.6,-0.75) 6(1.6,-0.25) 7(1.6,0.25) 8(1.6,0.75)
  silkscreen extent -1.05,-1.05 0.38,1.05, body extent -1.56,-1 1.56,1, height 0.9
